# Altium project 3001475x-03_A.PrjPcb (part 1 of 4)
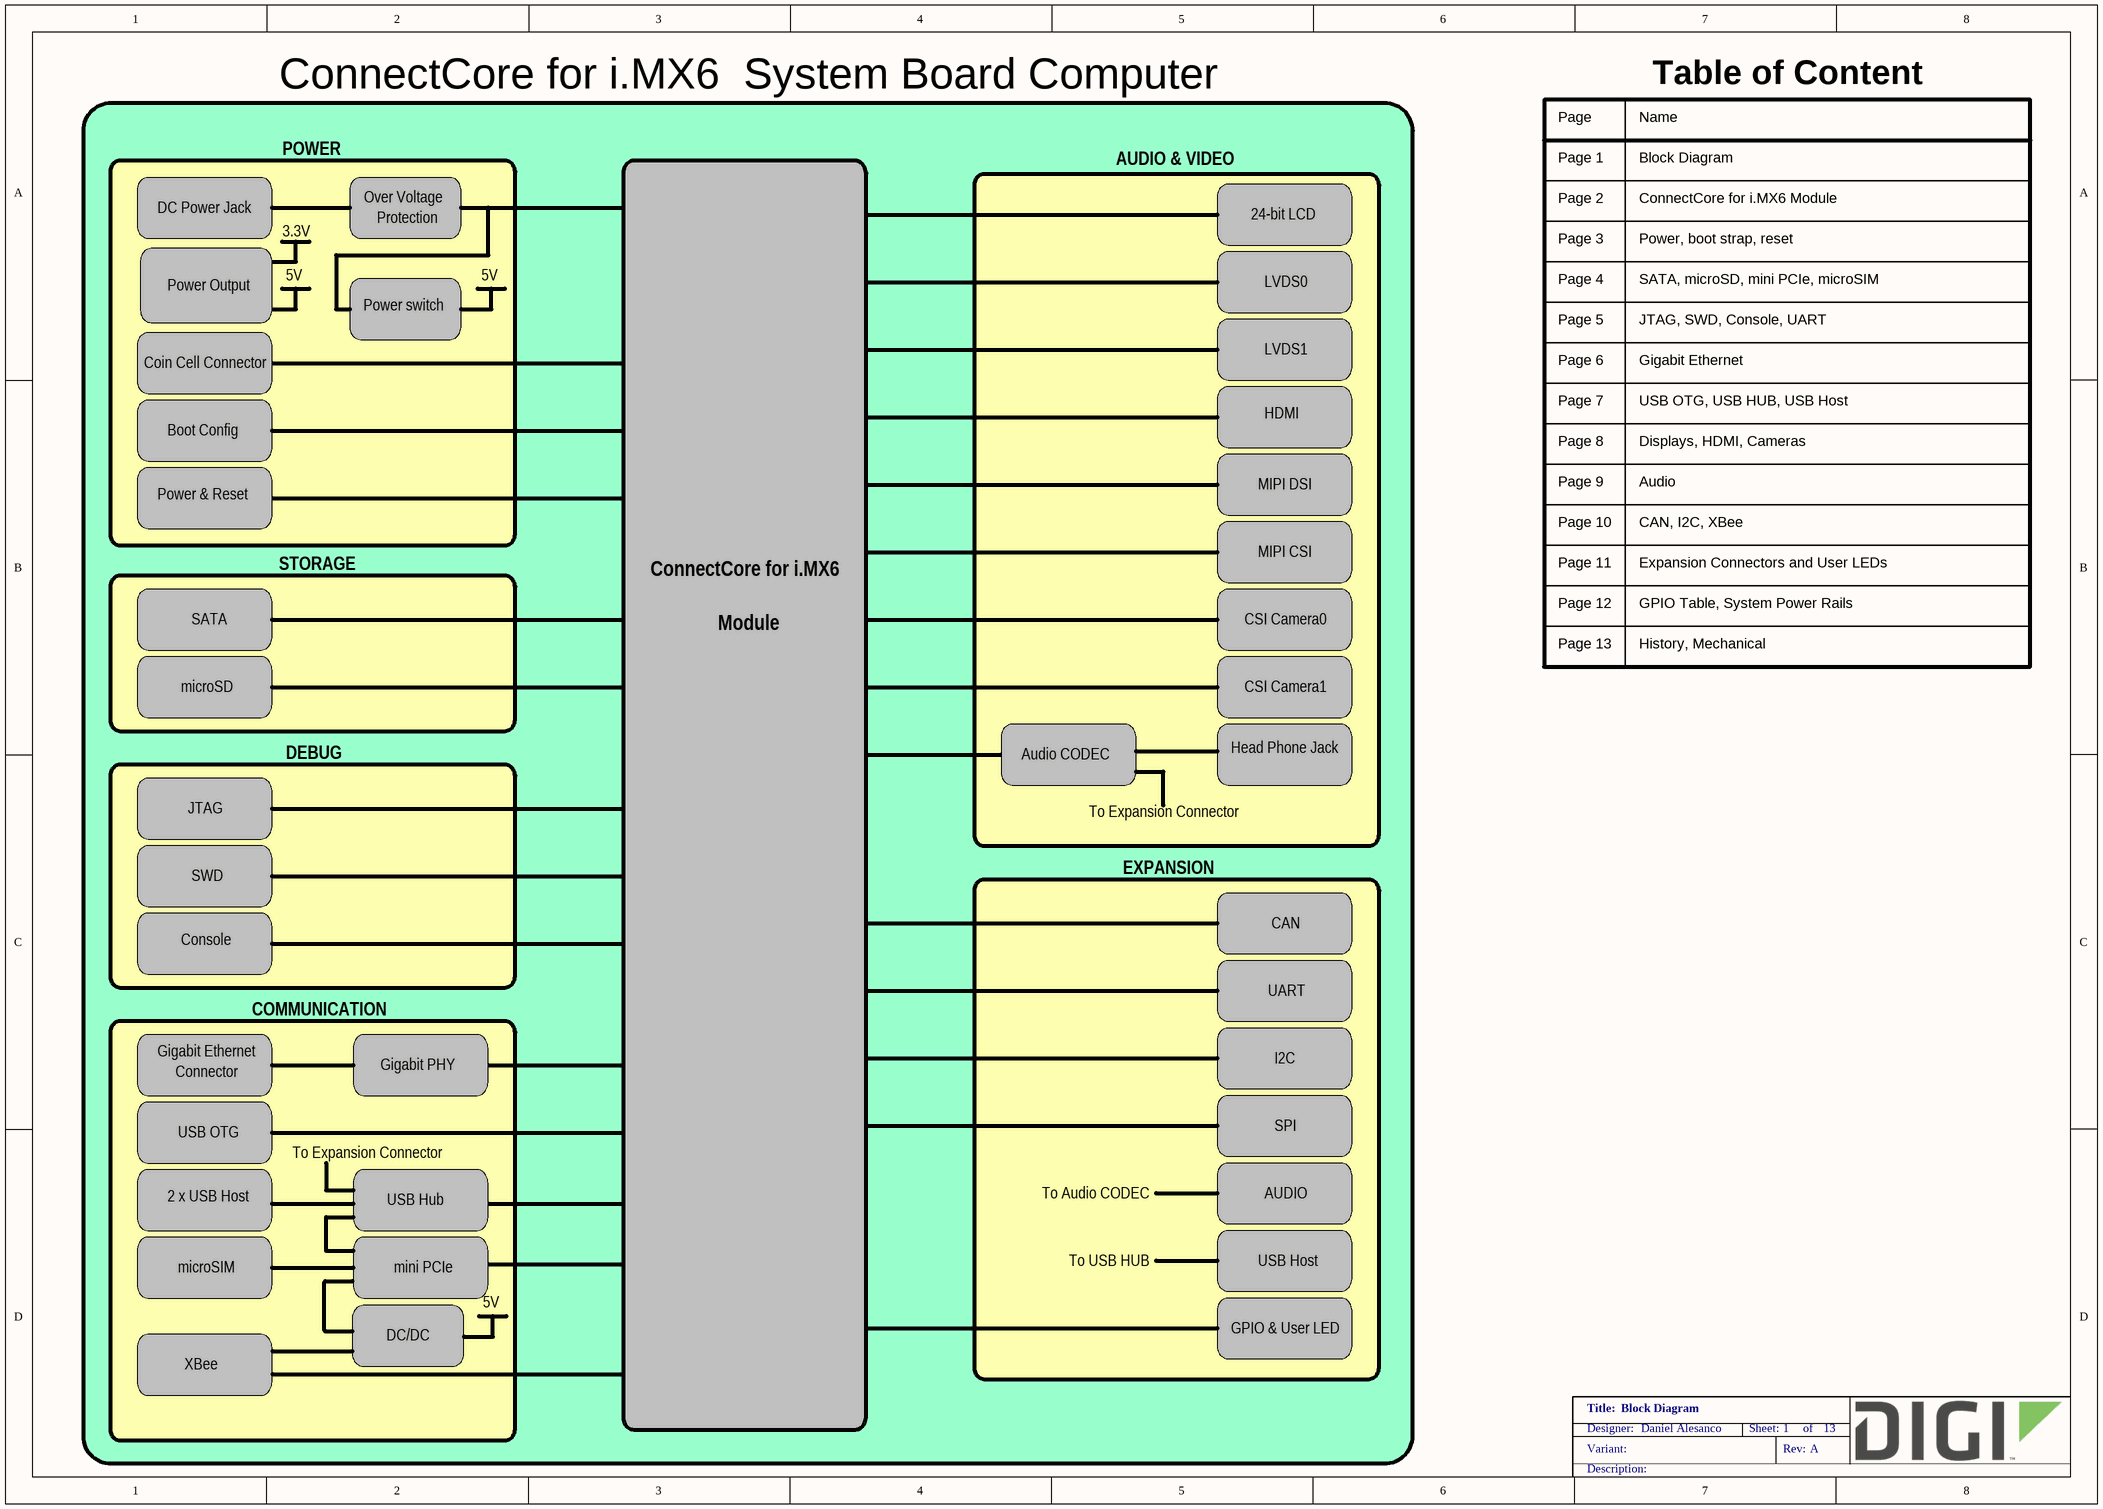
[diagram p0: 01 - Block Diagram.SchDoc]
VariantRevision: A
13 sheets, 433 parts. Net scope: flat (ports and power ports of the same name join across sheets).
Board file: 3001475x-03_A.PcbDoc
Sheets:
  01 - Block Diagram.SchDoc
  02 - CCIMX6 Module.SchDoc
  03 - Power, boot strap, reset.SchDoc
  04 - SATA, microSD, Mini PCIe, microSIM.SchDoc
  05 - JTAG, SWD, Console, UART.SchDoc
  06 - Gigabit Ethernet.SchDoc
  07 - USB OTG, USB HUB, USB Host.SchDoc
  08 - Displays, HDMI, Cameras.SchDoc
  09 - Audio.SchDoc
  10 - CAN, I2C, XBee.SchDoc
  11 - Expansion Connectors, User LEDs.SchDoc
  12 - GPIO Table, System Power rails.SchDoc
  13 - History, Mechanicals.SchDoc

## Sheet 01 - Block Diagram.SchDoc: Block Diagram
size A3; PageSetup: Record=PageOptions¦CenterHorizontal=True¦CenterVertical=True¦PrintScale=0.70¦XCorrection=1.00¦YCorrection=1.00¦PrintKind=0¦BorderSize=5000000¦LeftOffset=0¦BottomOffset=0¦Orientation=2¦PaperLength=4200¦PaperWidth=2970¦Scale=100¦PaperSource=7¦PrintQuality=600¦MediaType=1¦DitherType=10¦PaperKind=A4¦PrintScaleMode=1; Author: Daniel Alesanco; SheetNumber: 1; SheetTotal: 13

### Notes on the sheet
- ConnectCore for i.MX6  System Board Computer
- Table of Content
- POWER
- AUDIO & VIDEO
- Page 1
- Page
- Block Diagram
- Name
- DC Power Jack
- 3.3V
- Protection
- Over Voltage
- 24-bit LCD
- Page 2
- Page 3
- ConnectCore for i.MX6 Module
- Power, boot strap, reset
- Power Output
- 5V
- Power switch
- LVDS0
- Page 4
- SATA, microSD, mini PCIe, microSIM
- Coin Cell Connector
- LVDS1
- Page 5
- Page 6
- Gigabit Ethernet
- JTAG, SWD, Console, UART
- Boot Config
- HDMI
- Page 7
- Page 8
- Displays, HDMI, Cameras
- USB OTG, USB HUB, USB Host
- Power & Reset
- MIPI DSI
- Page 9
- Audio
- STORAGE
- ConnectCore for i.MX6
- MIPI CSI
- Page 10
- Page 11
- CAN, I2C, XBee
- Expansion Connectors and User LEDs
- SATA
- Module
- CSI Camera0
- Page 12
- Page 13
- GPIO Table, System Power Rails
- History, Mechanical
- microSD
- CSI Camera1
- DEBUG
- Audio CODEC
- Head Phone Jack
- JTAG
- To Expansion Connector
- SWD
- EXPANSION
- Console
- CAN
- COMMUNICATION
- UART
- Connector
- Gigabit PHY
- I2C
- USB OTG
- SPI
- 2 x USB Host
- USB Hub
- To Audio CODEC
- AUDIO
- microSIM
- mini PCIe
- To USB HUB
- USB Host
- XBee
- DC/DC
- GPIO & User LED

## Sheet 02 - CCIMX6 Module.SchDoc: ConnectCore for i.MX6 module
size A2; PageSetup: Record=PageOptions¦CenterHorizontal=True¦CenterVertical=True¦PrintScale=0.71¦XCorrection=1.00¦YCorrection=1.00¦PrintKind=0¦BorderSize=5000000¦LeftOffset=0¦BottomOffset=0¦Orientation=2¦PaperLength=4200¦PaperWidth=2970¦Scale=100¦PaperSource=7¦PrintQuality=600¦MediaType=1¦DitherType=10¦PaperKind=A3¦PrintScaleMode=1; Author: Daniel Alesanco; Organization: Altium Limited; Address1: L3, 12a Rodborough Rd; Address2: Frenchs Forest; Address3: NSW; Address4: Australia 2086; SheetNumber: 2; SheetTotal: 13
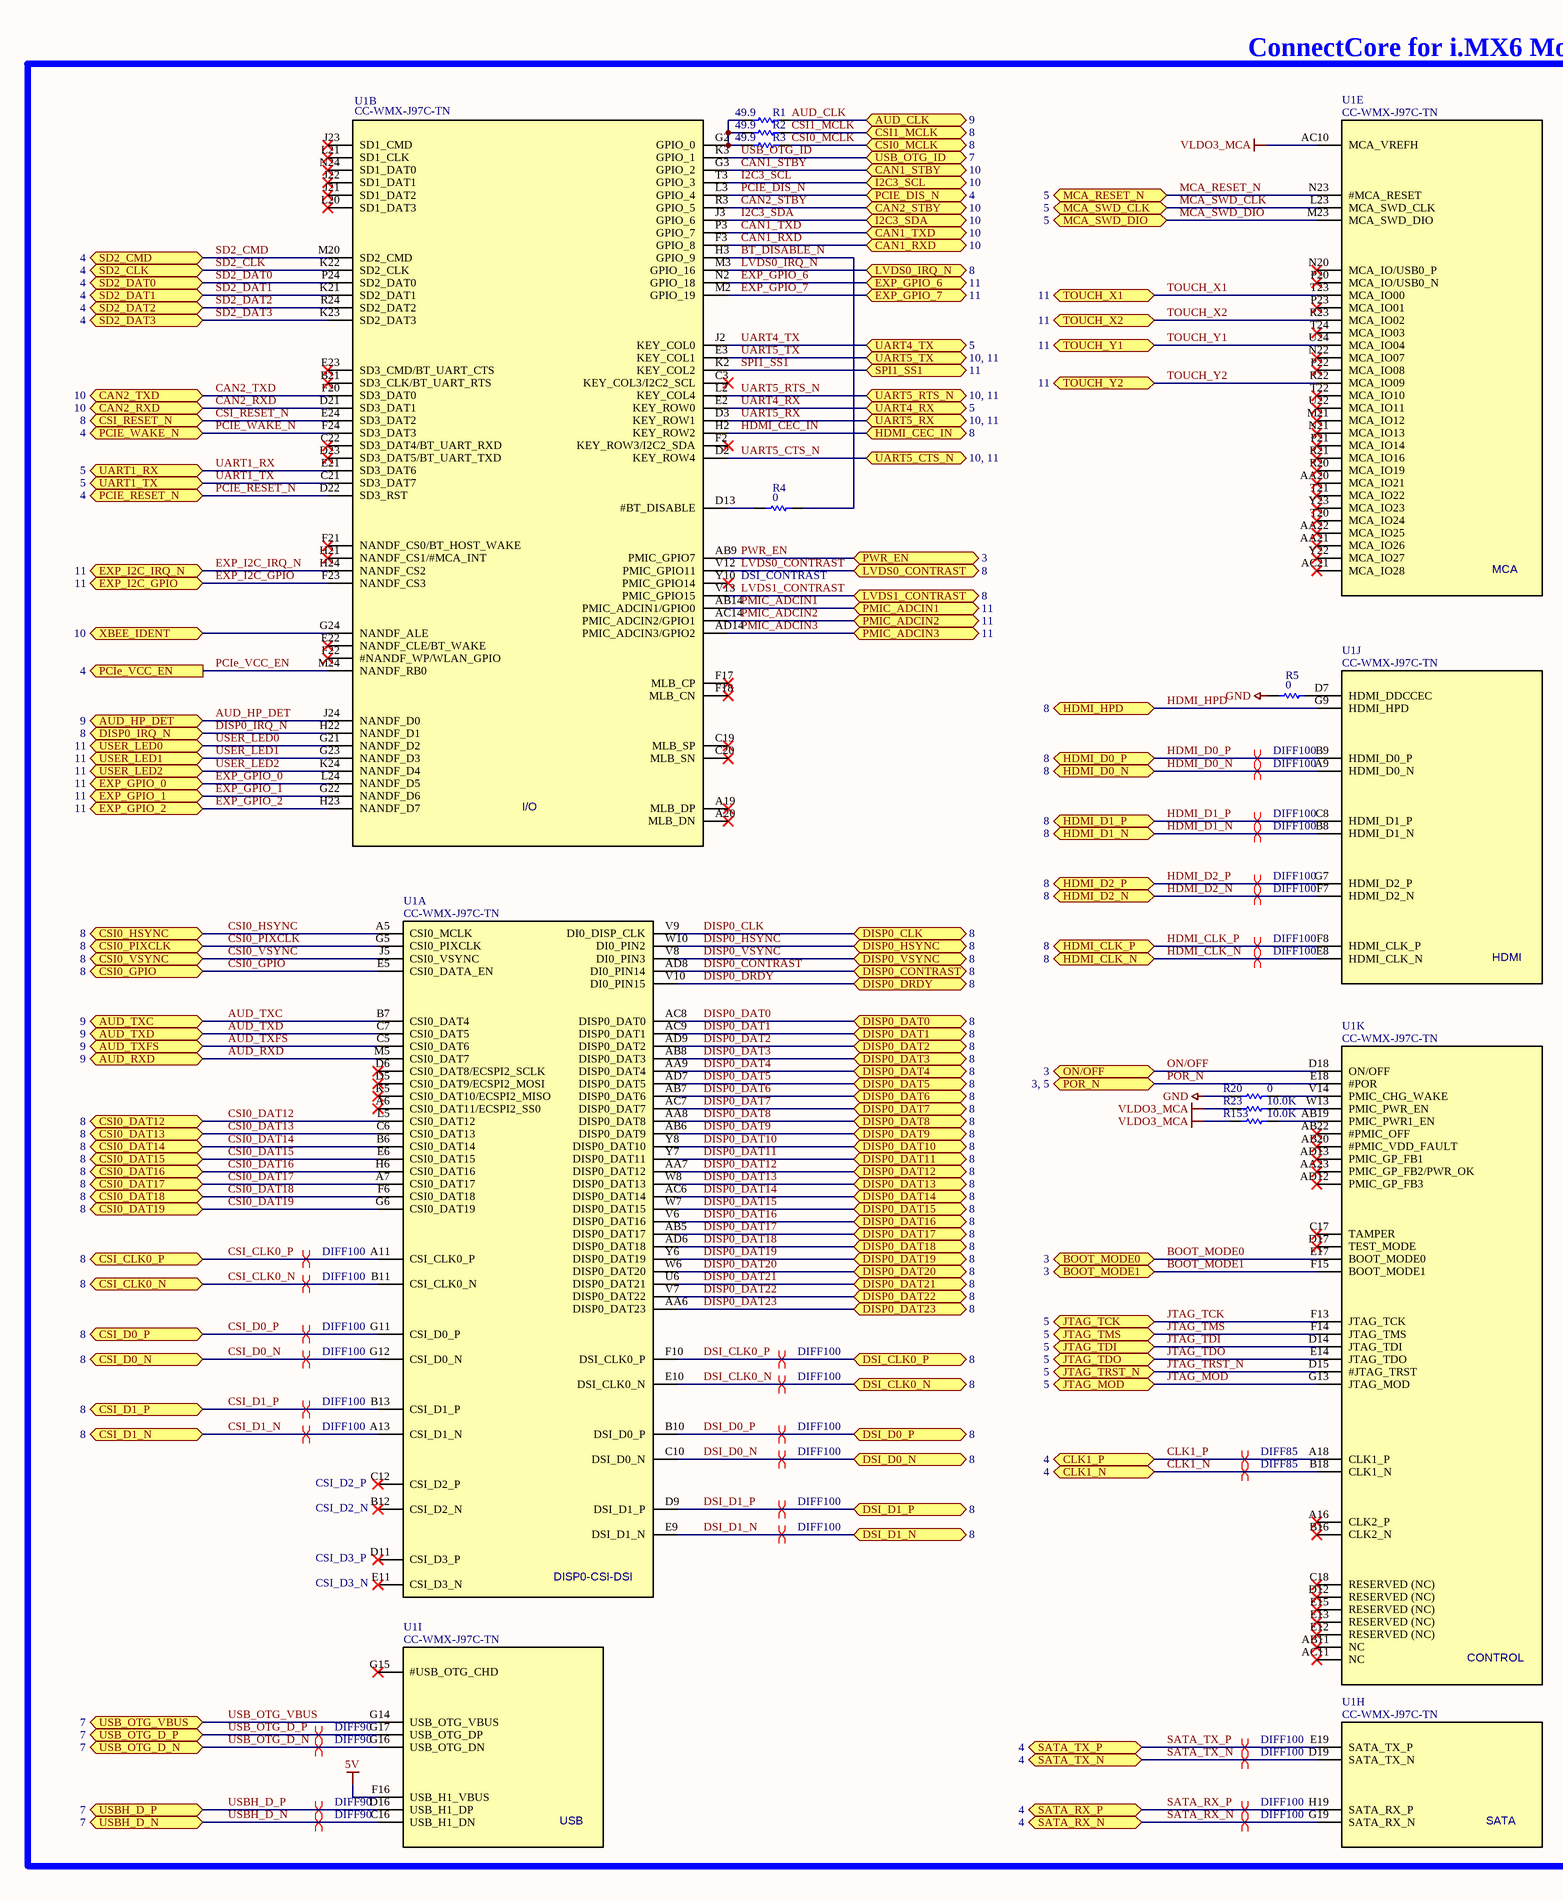
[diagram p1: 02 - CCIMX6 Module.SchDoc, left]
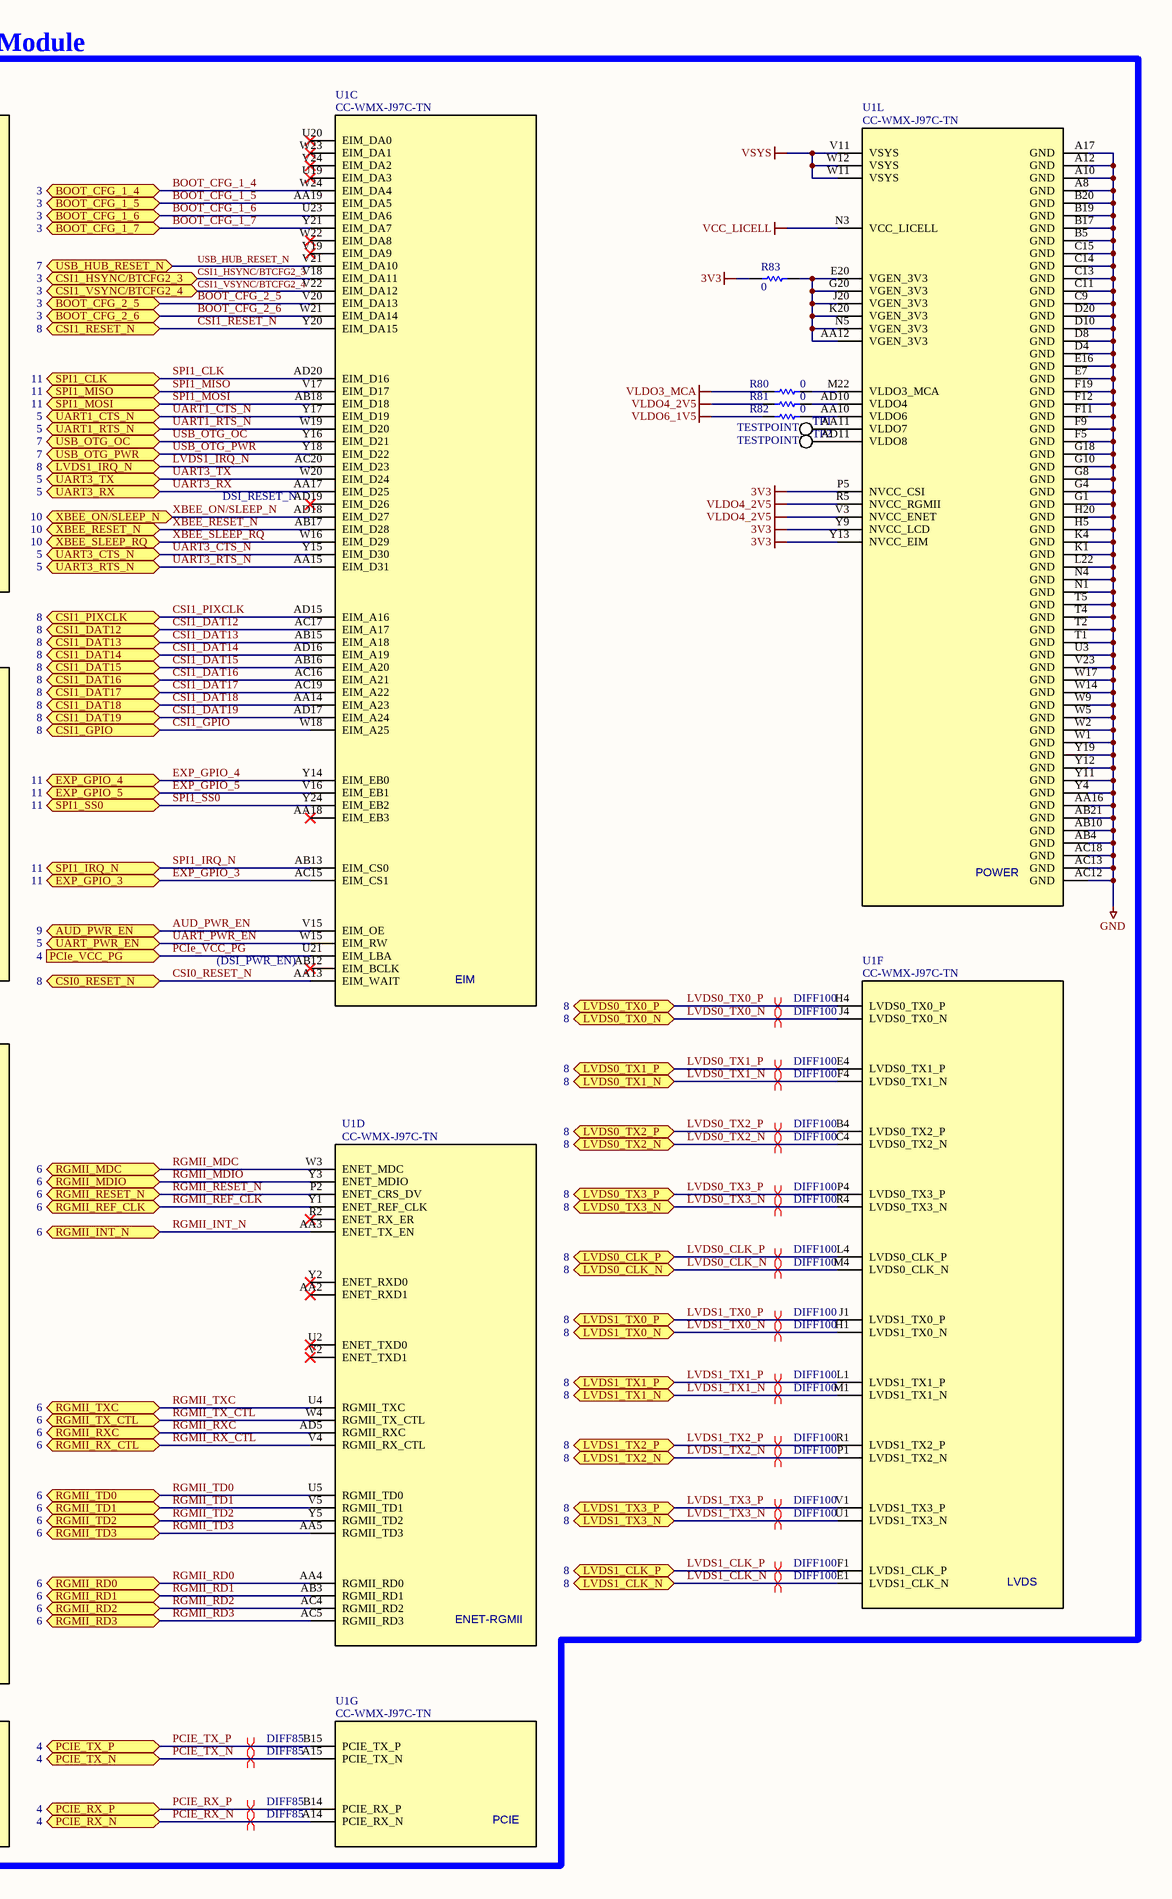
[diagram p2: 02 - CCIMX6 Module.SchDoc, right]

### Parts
R1  49.9  [RESC1005X40N]
R2  49.9  [RESC1005X40N]
R3  49.9  [RESC1005X40N]
R4  0  [RESC1005X40N]
R5  0  [RESC1005X40N]
R20  0  [RESC1005X40N]
R23  10.0K  [RESC1005X40N]
R80  0  [RESC1005X40N]
R81  0  [RESC1005X40N]
R82  0  [RESC1005X40N]
R83  0  [RESC1609X55N]
R153  10.0K  [RESC1005X40N]
TP1  TESTPOINT  [TP0762]  (no BOM)
TP2  TESTPOINT  [TP0762]  (no BOM)
U1  CC-WMX-J97C-TN  [MODULE_CCWMX6]  (parts A,B,C,D,E,F,G,H,I,J,K,L of 12)

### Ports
AUD_CLK (bidir, see 9), AUD_HP_DET (bidir, see 9), AUD_PWR_EN (bidir, see 9), AUD_RXD (bidir, see 9), AUD_TXC (bidir, see 9), AUD_TXD (bidir, see 9), AUD_TXFS (bidir, see 9), BOOT_CFG_1_4 (bidir, see 3), BOOT_CFG_1_5 (bidir, see 3), BOOT_CFG_1_6 (bidir, see 3), BOOT_CFG_1_7 (bidir, see 3), BOOT_CFG_2_5 (bidir, see 3), BOOT_CFG_2_6 (bidir, see 3), BOOT_MODE0 (bidir, see 3), BOOT_MODE1 (bidir, see 3), CAN1_RXD (bidir, see 10), CAN1_STBY (bidir, see 10), CAN1_TXD (bidir, see 10), CAN2_RXD (bidir, see 10), CAN2_STBY (bidir, see 10), CAN2_TXD (bidir, see 10), CLK1_N (bidir, see 4), CLK1_P (bidir, see 4), CSI0_DAT12 (bidir, see 8), CSI0_DAT13 (bidir, see 8), CSI0_DAT14 (bidir, see 8), CSI0_DAT15 (bidir, see 8), CSI0_DAT16 (bidir, see 8), CSI0_DAT17 (bidir, see 8), CSI0_DAT18 (bidir, see 8), CSI0_DAT19 (bidir, see 8), CSI0_GPIO (bidir, see 8), CSI0_HSYNC (bidir, see 8), CSI0_MCLK (bidir, see 8), CSI0_PIXCLK (bidir, see 8), CSI0_RESET_N (bidir, see 8), CSI0_VSYNC (bidir, see 8), CSI1_DAT12 (bidir, see 8), CSI1_DAT13 (bidir, see 8), CSI1_DAT14 (bidir, see 8), CSI1_DAT15 (bidir, see 8), CSI1_DAT16 (bidir, see 8), CSI1_DAT17 (bidir, see 8), CSI1_DAT18 (bidir, see 8), CSI1_DAT19 (bidir, see 8), CSI1_GPIO (bidir, see 8), CSI1_HSYNC/BTCFG2_3 (bidir, see 3), CSI1_MCLK (bidir, see 8), CSI1_PIXCLK (bidir, see 8), CSI1_RESET_N (bidir, see 8), CSI1_VSYNC/BTCFG2_4 (bidir, see 3), CSI_CLK0_N (bidir, see 8), CSI_CLK0_P (bidir, see 8), CSI_D0_N (bidir, see 8), CSI_D0_P (bidir, see 8), CSI_D1_N (bidir, see 8), CSI_D1_P (bidir, see 8), CSI_RESET_N (bidir, see 8), DISP0_CLK (bidir, see 8), DISP0_CONTRAST (bidir, see 8), DISP0_DAT0 (bidir, see 8), DISP0_DAT1 (bidir, see 8), DISP0_DAT2 (bidir, see 8), DISP0_DAT3 (bidir, see 8), DISP0_DAT4 (bidir, see 8), DISP0_DAT5 (bidir, see 8), DISP0_DAT6 (bidir, see 8), DISP0_DAT7 (bidir, see 8), DISP0_DAT8 (bidir, see 8), DISP0_DAT9 (bidir, see 8), DISP0_DAT10 (bidir, see 8), DISP0_DAT11 (bidir, see 8), DISP0_DAT12 (bidir, see 8), DISP0_DAT13 (bidir, see 8), DISP0_DAT14 (bidir, see 8), DISP0_DAT15 (bidir, see 8), DISP0_DAT16 (bidir, see 8), DISP0_DAT17 (bidir, see 8), DISP0_DAT18 (bidir, see 8), DISP0_DAT19 (bidir, see 8), DISP0_DAT20 (bidir, see 8), DISP0_DAT21 (bidir, see 8), DISP0_DAT22 (bidir, see 8), DISP0_DAT23 (bidir, see 8), DISP0_DRDY (bidir, see 8), DISP0_HSYNC (bidir, see 8), DISP0_IRQ_N (bidir, see 8), DISP0_VSYNC (bidir, see 8), DSI_CLK0_N (bidir, see 8), DSI_CLK0_P (bidir, see 8), DSI_D0_N (bidir, see 8), DSI_D0_P (bidir, see 8), DSI_D1_N (bidir, see 8), DSI_D1_P (bidir, see 8), EXP_GPIO_0 (bidir, see 11), EXP_GPIO_1 (bidir, see 11), EXP_GPIO_2 (bidir, see 11), EXP_GPIO_3 (bidir, see 11), EXP_GPIO_4 (bidir, see 11), EXP_GPIO_5 (bidir, see 11), EXP_GPIO_6 (bidir, see 11), EXP_GPIO_7 (bidir, see 11), EXP_I2C_GPIO (bidir, see 11), EXP_I2C_IRQ_N (bidir, see 11), HDMI_CEC_IN (bidir, see 8), HDMI_CLK_N (bidir, see 8), HDMI_CLK_P (bidir, see 8), HDMI_D0_N (bidir, see 8), HDMI_D0_P (bidir, see 8), HDMI_D1_N (bidir, see 8), HDMI_D1_P (bidir, see 8), HDMI_D2_N (bidir, see 8), HDMI_D2_P (bidir, see 8), HDMI_HPD (bidir, see 8), I2C3_SCL (bidir, see 10), I2C3_SDA (bidir, see 10), JTAG_MOD (bidir, see 5), JTAG_TCK (bidir, see 5), JTAG_TDI (bidir, see 5), JTAG_TDO (bidir, see 5), JTAG_TMS (bidir, see 5), JTAG_TRST_N (bidir, see 5), LVDS0_CLK_N (bidir, see 8), LVDS0_CLK_P (bidir, see 8), LVDS0_CONTRAST (bidir, see 8), LVDS0_IRQ_N (bidir, see 8), LVDS0_TX0_N (bidir, see 8), LVDS0_TX0_P (bidir, see 8), LVDS0_TX1_N (bidir, see 8), LVDS0_TX1_P (bidir, see 8), LVDS0_TX2_N (bidir, see 8), LVDS0_TX2_P (bidir, see 8), LVDS0_TX3_N (bidir, see 8), LVDS0_TX3_P (bidir, see 8), LVDS1_CLK_N (bidir, see 8), LVDS1_CLK_P (bidir, see 8), LVDS1_CONTRAST (bidir, see 8), LVDS1_IRQ_N (bidir, see 8), LVDS1_TX0_N (bidir, see 8), LVDS1_TX0_P (bidir, see 8), LVDS1_TX1_N (bidir, see 8), LVDS1_TX1_P (bidir, see 8), LVDS1_TX2_N (bidir, see 8), LVDS1_TX2_P (bidir, see 8), LVDS1_TX3_N (bidir, see 8), LVDS1_TX3_P (bidir, see 8), MCA_RESET_N (bidir, see 5), MCA_SWD_CLK (bidir, see 5), MCA_SWD_DIO (bidir, see 5), ON/OFF (bidir, see 3), PCIE_DIS_N (bidir, see 4), PCIE_RESET_N (bidir, see 4), PCIE_RX_N (bidir, see 4), PCIE_RX_P (bidir, see 4), PCIE_TX_N (bidir, see 4), PCIE_TX_P (bidir, see 4), PCIe_VCC_EN (out, see 4), PCIe_VCC_PG (in, see 4), PCIE_WAKE_N (bidir, see 4), PMIC_ADCIN1 (bidir, see 11), PMIC_ADCIN2 (bidir, see 11), PMIC_ADCIN3 (bidir, see 11), POR_N (bidir, see 3, 5), PWR_EN (bidir, see 3), RGMII_INT_N (bidir, see 6), RGMII_MDC (bidir, see 6), RGMII_MDIO (bidir, see 6), RGMII_RD0 (bidir, see 6), RGMII_RD1 (bidir, see 6), RGMII_RD2 (bidir, see 6), RGMII_RD3 (bidir, see 6), RGMII_REF_CLK (bidir, see 6), RGMII_RESET_N (bidir, see 6), RGMII_RX_CTL (bidir, see 6), RGMII_RXC (bidir, see 6), RGMII_TD0 (bidir, see 6), RGMII_TD1 (bidir, see 6), RGMII_TD2 (bidir, see 6), RGMII_TD3 (bidir, see 6), RGMII_TX_CTL (bidir, see 6), RGMII_TXC (bidir, see 6), SATA_RX_N (bidir, see 4), SATA_RX_P (bidir, see 4), SATA_TX_N (bidir, see 4), SATA_TX_P (bidir, see 4), SD2_CLK (bidir, see 4), SD2_CMD (bidir, see 4), SD2_DAT0 (bidir, see 4), SD2_DAT1 (bidir, see 4), SD2_DAT2 (bidir, see 4), SD2_DAT3 (bidir, see 4), SPI1_CLK (bidir, see 11), SPI1_IRQ_N (bidir, see 11), SPI1_MISO (bidir, see 11), SPI1_MOSI (bidir, see 11), SPI1_SS0 (bidir, see 11), SPI1_SS1 (bidir, see 11), TOUCH_X1 (bidir, see 11), TOUCH_X2 (bidir, see 11), TOUCH_Y1 (bidir, see 11), TOUCH_Y2 (bidir, see 11), UART1_CTS_N (bidir, see 5), UART1_RTS_N (bidir, see 5), UART1_RX (bidir, see 5), UART1_TX (bidir, see 5), UART3_CTS_N (bidir, see 5), UART3_RTS_N (bidir, see 5), UART3_RX (bidir, see 5), UART3_TX (bidir, see 5), UART4_RX (bidir, see 5), UART4_TX (bidir, see 5), UART5_CTS_N (bidir, see 10, 11), UART5_RTS_N (bidir, see 10, 11), UART5_RX (bidir, see 10, 11), UART5_TX (bidir, see 10, 11), UART_PWR_EN (bidir, see 5), USB_HUB_RESET_N (bidir, see 7), USB_OTG_D_N (bidir, see 7), USB_OTG_D_P (bidir, see 7), USB_OTG_ID (bidir, see 7), USB_OTG_OC (bidir, see 7), USB_OTG_PWR (bidir, see 7), USB_OTG_VBUS (bidir, see 7), USBH_D_N (bidir, see 7), USBH_D_P (bidir, see 7), USER_LED0 (bidir, see 11), USER_LED1 (bidir, see 11), USER_LED2 (bidir, see 11), XBEE_IDENT (bidir, see 10), XBEE_ON/SLEEP_N (bidir, see 10), XBEE_RESET_N (bidir, see 10), XBEE_SLEEP_RQ (bidir, see 10)

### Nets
3V3: R83.1 U1.P5(NVCC_CSI) U1.Y9(NVCC_LCD) U1.Y13(NVCC_EIM)
5V: U1.F16(USB_H1_VBUS)
GND: R5.1 R20.1 U1.A8(GND) U1.A10(GND) U1.A12(GND) U1.A17(GND) U1.AA16(GND) U1.AB4(GND) U1.AB10(GND) U1.AB21(GND) U1.AC12(GND) U1.AC13(GND) U1.AC18(GND) U1.B5(GND) U1.B17(GND) U1.B19(GND) U1.B20(GND) U1.C9(GND) U1.C11(GND) U1.C13(GND) U1.C14(GND) U1.C15(GND) U1.D4(GND) U1.D8(GND) U1.D10(GND) U1.D20(GND) U1.E7(GND) U1.E16(GND) U1.F5(GND) U1.F9(GND) U1.F11(GND) U1.F12(GND) U1.F19(GND) U1.G1(GND) U1.G4(GND) U1.G8(GND) U1.G10(GND) U1.G18(GND) U1.H5(GND) U1.H20(GND) U1.K1(GND) U1.K4(GND) U1.L22(GND) U1.N1(GND) U1.N4(GND) U1.T1(GND) U1.T2(GND) U1.T4(GND) U1.T5(GND) U1.U3(GND) U1.V23(GND) U1.W1(GND) U1.W2(GND) U1.W5(GND) U1.W9(GND) U1.W14(GND) U1.W17(GND) U1.Y4(GND) U1.Y11(GND) U1.Y12(GND) U1.Y19(GND)
VCC_LICELL: U1.N3(VCC_LICELL)
VLDO3_MCA: R23.2 R80.1 R153.2 U1.AC10(MCA_VREFH)
VLDO4_2V5: R81.1 U1.R5(NVCC_RGMII) U1.V3(NVCC_ENET)
VLDO6_1V5: R82.1
VSYS: U1.V11(VSYS) U1.W11(VSYS) U1.W12(VSYS)
AUD_CLK: R1.2 ; port AUD_CLK
AUD_HP_DET: U1.J24(NANDF_D0) ; port AUD_HP_DET
AUD_PWR_EN: U1.V15(EIM_OE) ; port AUD_PWR_EN
AUD_RXD: U1.M5(CSI0_DAT7) ; port AUD_RXD
AUD_TXC: U1.B7(CSI0_DAT4) ; port AUD_TXC
AUD_TXD: U1.C7(CSI0_DAT5) ; port AUD_TXD
AUD_TXFS: U1.C5(CSI0_DAT6) ; port AUD_TXFS
BOOT_CFG_1_4: U1.W24(EIM_DA4) ; port BOOT_CFG_1_4
BOOT_CFG_1_5: U1.AA19(EIM_DA5) ; port BOOT_CFG_1_5
BOOT_CFG_1_6: U1.U23(EIM_DA6) ; port BOOT_CFG_1_6
BOOT_CFG_1_7: U1.Y21(EIM_DA7) ; port BOOT_CFG_1_7
BOOT_CFG_2_5: U1.V20(EIM_DA13) ; port BOOT_CFG_2_5
BOOT_CFG_2_6: U1.W21(EIM_DA14) ; port BOOT_CFG_2_6
BOOT_MODE0: U1.E17(BOOT_MODE0) ; port BOOT_MODE0
BOOT_MODE1: U1.F15(BOOT_MODE1) ; port BOOT_MODE1
BT_DISABLE_N: R4.2 U1.H3(GPIO_9)
CAN1_RXD: U1.F3(GPIO_8) ; port CAN1_RXD
CAN1_STBY: U1.G3(GPIO_2) ; port CAN1_STBY
CAN1_TXD: U1.P3(GPIO_7) ; port CAN1_TXD
CAN2_RXD: U1.D21(SD3_DAT1) ; port CAN2_RXD
CAN2_STBY: U1.R3(GPIO_5) ; port CAN2_STBY
CAN2_TXD: U1.F20(SD3_DAT0) ; port CAN2_TXD
CLK1_N: U1.B18(CLK1_N) ; port CLK1_N
CLK1_P: U1.A18(CLK1_P) ; port CLK1_P
CSI0_DAT12: U1.L5(CSI0_DAT12) ; port CSI0_DAT12
CSI0_DAT13: U1.C6(CSI0_DAT13) ; port CSI0_DAT13
CSI0_DAT14: U1.B6(CSI0_DAT14) ; port CSI0_DAT14
CSI0_DAT15: U1.E6(CSI0_DAT15) ; port CSI0_DAT15
CSI0_DAT16: U1.H6(CSI0_DAT16) ; port CSI0_DAT16
CSI0_DAT17: U1.A7(CSI0_DAT17) ; port CSI0_DAT17
CSI0_DAT18: U1.F6(CSI0_DAT18) ; port CSI0_DAT18
CSI0_DAT19: U1.G6(CSI0_DAT19) ; port CSI0_DAT19
CSI0_GPIO: U1.E5(CSI0_DATA_EN) ; port CSI0_GPIO
CSI0_HSYNC: U1.A5(CSI0_MCLK) ; port CSI0_HSYNC
CSI0_MCLK: R3.2 ; port CSI0_MCLK
CSI0_PIXCLK: U1.G5(CSI0_PIXCLK) ; port CSI0_PIXCLK
CSI0_RESET_N: U1.AA13(EIM_WAIT) ; port CSI0_RESET_N
CSI0_VSYNC: U1.J5(CSI0_VSYNC) ; port CSI0_VSYNC
CSI1_DAT12: U1.AC17(EIM_A17) ; port CSI1_DAT12
CSI1_DAT13: U1.AB15(EIM_A18) ; port CSI1_DAT13
CSI1_DAT14: U1.AD16(EIM_A19) ; port CSI1_DAT14
CSI1_DAT15: U1.AB16(EIM_A20) ; port CSI1_DAT15
CSI1_DAT16: U1.AC16(EIM_A21) ; port CSI1_DAT16
CSI1_DAT17: U1.AC19(EIM_A22) ; port CSI1_DAT17
CSI1_DAT18: U1.AA14(EIM_A23) ; port CSI1_DAT18
CSI1_DAT19: U1.AD17(EIM_A24) ; port CSI1_DAT19
CSI1_GPIO: U1.W18(EIM_A25) ; port CSI1_GPIO
CSI1_HSYNC/BTCFG2_3: U1.V18(EIM_DA11) ; port CSI1_HSYNC/BTCFG2_3
CSI1_MCLK: R2.2 ; port CSI1_MCLK
CSI1_PIXCLK: U1.AD15(EIM_A16) ; port CSI1_PIXCLK
CSI1_RESET_N: U1.Y20(EIM_DA15) ; port CSI1_RESET_N
CSI1_VSYNC/BTCFG2_4: U1.V22(EIM_DA12) ; port CSI1_VSYNC/BTCFG2_4
CSI_CLK0_N: U1.B11(CSI_CLK0_N) ; port CSI_CLK0_N
CSI_CLK0_P: U1.A11(CSI_CLK0_P) ; port CSI_CLK0_P
CSI_D0_N: U1.G12(CSI_D0_N) ; port CSI_D0_N
CSI_D0_P: U1.G11(CSI_D0_P) ; port CSI_D0_P
CSI_D1_N: U1.A13(CSI_D1_N) ; port CSI_D1_N
CSI_D1_P: U1.B13(CSI_D1_P) ; port CSI_D1_P
CSI_RESET_N: U1.E24(SD3_DAT2) ; port CSI_RESET_N
DISP0_CLK: U1.V9(DI0_DISP_CLK) ; port DISP0_CLK
DISP0_CONTRAST: U1.AD8(DI0_PIN14) ; port DISP0_CONTRAST
DISP0_DAT0: U1.AC8(DISP0_DAT0) ; port DISP0_DAT0
DISP0_DAT1: U1.AC9(DISP0_DAT1) ; port DISP0_DAT1
DISP0_DAT2: U1.AD9(DISP0_DAT2) ; port DISP0_DAT2
DISP0_DAT3: U1.AB8(DISP0_DAT3) ; port DISP0_DAT3
DISP0_DAT4: U1.AA9(DISP0_DAT4) ; port DISP0_DAT4
DISP0_DAT5: U1.AD7(DISP0_DAT5) ; port DISP0_DAT5
DISP0_DAT6: U1.AB7(DISP0_DAT6) ; port DISP0_DAT6
DISP0_DAT7: U1.AC7(DISP0_DAT7) ; port DISP0_DAT7
DISP0_DAT8: U1.AA8(DISP0_DAT8) ; port DISP0_DAT8
DISP0_DAT9: U1.AB6(DISP0_DAT9) ; port DISP0_DAT9
DISP0_DAT10: U1.Y8(DISP0_DAT10) ; port DISP0_DAT10
DISP0_DAT11: U1.Y7(DISP0_DAT11) ; port DISP0_DAT11
DISP0_DAT12: U1.AA7(DISP0_DAT12) ; port DISP0_DAT12
DISP0_DAT13: U1.W8(DISP0_DAT13) ; port DISP0_DAT13
DISP0_DAT14: U1.AC6(DISP0_DAT14) ; port DISP0_DAT14
DISP0_DAT15: U1.W7(DISP0_DAT15) ; port DISP0_DAT15
DISP0_DAT16: U1.V6(DISP0_DAT16) ; port DISP0_DAT16
DISP0_DAT17: U1.AB5(DISP0_DAT17) ; port DISP0_DAT17
DISP0_DAT18: U1.AD6(DISP0_DAT18) ; port DISP0_DAT18
DISP0_DAT19: U1.Y6(DISP0_DAT19) ; port DISP0_DAT19
DISP0_DAT20: U1.W6(DISP0_DAT20) ; port DISP0_DAT20
DISP0_DAT21: U1.U6(DISP0_DAT21) ; port DISP0_DAT21
DISP0_DAT22: U1.V7(DISP0_DAT22) ; port DISP0_DAT22
DISP0_DAT23: U1.AA6(DISP0_DAT23) ; port DISP0_DAT23
DISP0_DRDY: U1.V10(DI0_PIN15) ; port DISP0_DRDY
DISP0_HSYNC: U1.W10(DI0_PIN2) ; port DISP0_HSYNC
DISP0_IRQ_N: U1.H22(NANDF_D1) ; port DISP0_IRQ_N
DISP0_VSYNC: U1.V8(DI0_PIN3) ; port DISP0_VSYNC
DSI_CLK0_N: U1.E10(DSI_CLK0_N) ; port DSI_CLK0_N
DSI_CLK0_P: U1.F10(DSI_CLK0_P) ; port DSI_CLK0_P
DSI_D0_N: U1.C10(DSI_D0_N) ; port DSI_D0_N
DSI_D0_P: U1.B10(DSI_D0_P) ; port DSI_D0_P
DSI_D1_N: U1.E9(DSI_D1_N) ; port DSI_D1_N
DSI_D1_P: U1.D9(DSI_D1_P) ; port DSI_D1_P
EXP_GPIO_0: U1.L24(NANDF_D5) ; port EXP_GPIO_0
EXP_GPIO_1: U1.G22(NANDF_D6) ; port EXP_GPIO_1
EXP_GPIO_2: U1.H23(NANDF_D7) ; port EXP_GPIO_2
EXP_GPIO_3: U1.AC15(EIM_CS1) ; port EXP_GPIO_3
EXP_GPIO_4: U1.Y14(EIM_EB0) ; port EXP_GPIO_4
EXP_GPIO_5: U1.V16(EIM_EB1) ; port EXP_GPIO_5
EXP_GPIO_6: U1.N2(GPIO_18) ; port EXP_GPIO_6
EXP_GPIO_7: U1.M2(GPIO_19) ; port EXP_GPIO_7
EXP_I2C_GPIO: U1.F23(NANDF_CS3) ; port EXP_I2C_GPIO
EXP_I2C_IRQ_N: U1.H24(NANDF_CS2) ; port EXP_I2C_IRQ_N
HDMI_CEC_IN: U1.H2(KEY_ROW2) ; port HDMI_CEC_IN
HDMI_CLK_N: U1.E8(HDMI_CLK_N) ; port HDMI_CLK_N
HDMI_CLK_P: U1.F8(HDMI_CLK_P) ; port HDMI_CLK_P
HDMI_D0_N: U1.A9(HDMI_D0_N) ; port HDMI_D0_N
HDMI_D0_P: U1.B9(HDMI_D0_P) ; port HDMI_D0_P
HDMI_D1_N: U1.B8(HDMI_D1_N) ; port HDMI_D1_N
HDMI_D1_P: U1.C8(HDMI_D1_P) ; port HDMI_D1_P
HDMI_D2_N: U1.F7(HDMI_D2_N) ; port HDMI_D2_N
HDMI_D2_P: U1.G7(HDMI_D2_P) ; port HDMI_D2_P
HDMI_HPD: U1.G9(HDMI_HPD) ; port HDMI_HPD
I2C3_SCL: U1.T3(GPIO_3) ; port I2C3_SCL
I2C3_SDA: U1.J3(GPIO_6) ; port I2C3_SDA
JTAG_MOD: U1.G13(JTAG_MOD) ; port JTAG_MOD
JTAG_TCK: U1.F13(JTAG_TCK) ; port JTAG_TCK
JTAG_TDI: U1.D14(JTAG_TDI) ; port JTAG_TDI
JTAG_TDO: U1.E14(JTAG_TDO) ; port JTAG_TDO
JTAG_TMS: U1.F14(JTAG_TMS) ; port JTAG_TMS
JTAG_TRST_N: U1.D15(#JTAG_TRST) ; port JTAG_TRST_N
LVDS0_CLK_N: U1.M4(LVDS0_CLK_N) ; port LVDS0_CLK_N
LVDS0_CLK_P: U1.L4(LVDS0_CLK_P) ; port LVDS0_CLK_P
LVDS0_CONTRAST: U1.V12(PMIC_GPIO11) ; port LVDS0_CONTRAST
LVDS0_IRQ_N: U1.M3(GPIO_16) ; port LVDS0_IRQ_N
LVDS0_TX0_N: U1.J4(LVDS0_TX0_N) ; port LVDS0_TX0_N
LVDS0_TX0_P: U1.H4(LVDS0_TX0_P) ; port LVDS0_TX0_P
LVDS0_TX1_N: U1.F4(LVDS0_TX1_N) ; port LVDS0_TX1_N
LVDS0_TX1_P: U1.E4(LVDS0_TX1_P) ; port LVDS0_TX1_P
LVDS0_TX2_N: U1.C4(LVDS0_TX2_N) ; port LVDS0_TX2_N
LVDS0_TX2_P: U1.B4(LVDS0_TX2_P) ; port LVDS0_TX2_P
LVDS0_TX3_N: U1.R4(LVDS0_TX3_N) ; port LVDS0_TX3_N
LVDS0_TX3_P: U1.P4(LVDS0_TX3_P) ; port LVDS0_TX3_P
LVDS1_CLK_N: U1.E1(LVDS1_CLK_N) ; port LVDS1_CLK_N
LVDS1_CLK_P: U1.F1(LVDS1_CLK_P) ; port LVDS1_CLK_P
LVDS1_CONTRAST: U1.V13(PMIC_GPIO15) ; port LVDS1_CONTRAST
LVDS1_IRQ_N: U1.AC20(EIM_D23) ; port LVDS1_IRQ_N
LVDS1_TX0_N: U1.H1(LVDS1_TX0_N) ; port LVDS1_TX0_N
LVDS1_TX0_P: U1.J1(LVDS1_TX0_P) ; port LVDS1_TX0_P
LVDS1_TX1_N: U1.M1(LVDS1_TX1_N) ; port LVDS1_TX1_N
LVDS1_TX1_P: U1.L1(LVDS1_TX1_P) ; port LVDS1_TX1_P
LVDS1_TX2_N: U1.P1(LVDS1_TX2_N) ; port LVDS1_TX2_N
LVDS1_TX2_P: U1.R1(LVDS1_TX2_P) ; port LVDS1_TX2_P
LVDS1_TX3_N: U1.U1(LVDS1_TX3_N) ; port LVDS1_TX3_N
LVDS1_TX3_P: U1.V1(LVDS1_TX3_P) ; port LVDS1_TX3_P
MCA_RESET_N: U1.N23(#MCA_RESET) ; port MCA_RESET_N
MCA_SWD_CLK: U1.L23(MCA_SWD_CLK) ; port MCA_SWD_CLK
MCA_SWD_DIO: U1.M23(MCA_SWD_DIO) ; port MCA_SWD_DIO
ON/OFF: U1.D18(ON/OFF) ; port ON/OFF
PCIE_DIS_N: U1.L3(GPIO_4) ; port PCIE_DIS_N
PCIE_RESET_N: U1.D22(SD3_RST) ; port PCIE_RESET_N
PCIE_RX_N: U1.A14(PCIE_RX_N) ; port PCIE_RX_N
PCIE_RX_P: U1.B14(PCIE_RX_P) ; port PCIE_RX_P
PCIE_TX_N: U1.A15(PCIE_TX_N) ; port PCIE_TX_N
PCIE_TX_P: U1.B15(PCIE_TX_P) ; port PCIE_TX_P
PCIe_VCC_EN: U1.M24(NANDF_RB0) ; port PCIe_VCC_EN
PCIe_VCC_PG: U1.U21(EIM_LBA) ; port PCIe_VCC_PG
PCIE_WAKE_N: U1.F24(SD3_DAT3) ; port PCIE_WAKE_N
PMIC_ADCIN1: U1.AB14(PMIC_ADCIN1/GPIO0) ; port PMIC_ADCIN1
PMIC_ADCIN2: U1.AC14(PMIC_ADCIN2/GPIO1) ; port PMIC_ADCIN2
PMIC_ADCIN3: U1.AD14(PMIC_ADCIN3/GPIO2) ; port PMIC_ADCIN3
POR_N: U1.E18(#POR) ; port POR_N
PWR_EN: U1.AB9(PMIC_GPIO7) ; port PWR_EN
RGMII_INT_N: U1.AA3(ENET_TX_EN) ; port RGMII_INT_N
RGMII_MDC: U1.W3(ENET_MDC) ; port RGMII_MDC
RGMII_MDIO: U1.Y3(ENET_MDIO) ; port RGMII_MDIO
RGMII_RD0: U1.AA4(RGMII_RD0) ; port RGMII_RD0
RGMII_RD1: U1.AB3(RGMII_RD1) ; port RGMII_RD1
RGMII_RD2: U1.AC4(RGMII_RD2) ; port RGMII_RD2
RGMII_RD3: U1.AC5(RGMII_RD3) ; port RGMII_RD3
RGMII_REF_CLK: U1.Y1(ENET_REF_CLK) ; port RGMII_REF_CLK
RGMII_RESET_N: U1.P2(ENET_CRS_DV) ; port RGMII_RESET_N
RGMII_RX_CTL: U1.V4(RGMII_RX_CTL) ; port RGMII_RX_CTL
RGMII_RXC: U1.AD5(RGMII_RXC) ; port RGMII_RXC
RGMII_TD0: U1.U5(RGMII_TD0) ; port RGMII_TD0
RGMII_TD1: U1.V5(RGMII_TD1) ; port RGMII_TD1
RGMII_TD2: U1.Y5(RGMII_TD2) ; port RGMII_TD2
RGMII_TD3: U1.AA5(RGMII_TD3) ; port RGMII_TD3
RGMII_TX_CTL: U1.W4(RGMII_TX_CTL) ; port RGMII_TX_CTL
RGMII_TXC: U1.U4(RGMII_TXC) ; port RGMII_TXC
SATA_RX_N: U1.G19(SATA_RX_N) ; port SATA_RX_N
SATA_RX_P: U1.H19(SATA_RX_P) ; port SATA_RX_P
SATA_TX_N: U1.D19(SATA_TX_N) ; port SATA_TX_N
SATA_TX_P: U1.E19(SATA_TX_P) ; port SATA_TX_P
SD2_CLK: U1.K22(SD2_CLK) ; port SD2_CLK
SD2_CMD: U1.M20(SD2_CMD) ; port SD2_CMD
SD2_DAT0: U1.P24(SD2_DAT0) ; port SD2_DAT0
SD2_DAT1: U1.K21(SD2_DAT1) ; port SD2_DAT1
SD2_DAT2: U1.R24(SD2_DAT2) ; port SD2_DAT2
SD2_DAT3: U1.K23(SD2_DAT3) ; port SD2_DAT3
SPI1_CLK: U1.AD20(EIM_D16) ; port SPI1_CLK
SPI1_IRQ_N: U1.AB13(EIM_CS0) ; port SPI1_IRQ_N
SPI1_MISO: U1.V17(EIM_D17) ; port SPI1_MISO
SPI1_MOSI: U1.AB18(EIM_D18) ; port SPI1_MOSI
SPI1_SS0: U1.Y24(EIM_EB2) ; port SPI1_SS0
SPI1_SS1: U1.K2(KEY_COL2) ; port SPI1_SS1
TOUCH_X1: U1.T23(MCA_IO00) ; port TOUCH_X1
TOUCH_X2: U1.R23(MCA_IO02) ; port TOUCH_X2
TOUCH_Y1: U1.U24(MCA_IO04) ; port TOUCH_Y1
TOUCH_Y2: U1.R22(MCA_IO09) ; port TOUCH_Y2
UART1_CTS_N: U1.Y17(EIM_D19) ; port UART1_CTS_N
UART1_RTS_N: U1.W19(EIM_D20) ; port UART1_RTS_N
UART1_RX: U1.E21(SD3_DAT6) ; port UART1_RX
UART1_TX: U1.C21(SD3_DAT7) ; port UART1_TX
UART3_CTS_N: U1.Y15(EIM_D30) ; port UART3_CTS_N
UART3_RTS_N: U1.AA15(EIM_D31) ; port UART3_RTS_N
UART3_RX: U1.AA17(EIM_D25) ; port UART3_RX
UART3_TX: U1.W20(EIM_D24) ; port UART3_TX
UART4_RX: U1.E2(KEY_ROW0) ; port UART4_RX
UART4_TX: U1.J2(KEY_COL0) ; port UART4_TX
UART5_CTS_N: U1.D2(KEY_ROW4) ; port UART5_CTS_N
UART5_RTS_N: U1.L2(KEY_COL4) ; port UART5_RTS_N
UART5_RX: U1.D3(KEY_ROW1) ; port UART5_RX
UART5_TX: U1.E3(KEY_COL1) ; port UART5_TX
UART_PWR_EN: U1.W15(EIM_RW) ; port UART_PWR_EN
USB_HUB_RESET_N: U1.V21(EIM_DA10) ; port USB_HUB_RESET_N
USB_OTG_D_N: U1.G16(USB_OTG_DN) ; port USB_OTG_D_N
USB_OTG_D_P: U1.G17(USB_OTG_DP) ; port USB_OTG_D_P
USB_OTG_ID: U1.K3(GPIO_1) ; port USB_OTG_ID
USB_OTG_OC: U1.Y16(EIM_D21) ; port USB_OTG_OC
USB_OTG_PWR: U1.Y18(EIM_D22) ; port USB_OTG_PWR
USB_OTG_VBUS: U1.G14(USB_OTG_VBUS) ; port USB_OTG_VBUS
USBH_D_N: U1.C16(USB_H1_DN) ; port USBH_D_N
USBH_D_P: U1.D16(USB_H1_DP) ; port USBH_D_P
USER_LED0: U1.G21(NANDF_D2) ; port USER_LED0
USER_LED1: U1.G23(NANDF_D3) ; port USER_LED1
USER_LED2: U1.K24(NANDF_D4) ; port USER_LED2
XBEE_IDENT: U1.G24(NANDF_ALE) ; port XBEE_IDENT
XBEE_ON/SLEEP_N: U1.AD18(EIM_D27) ; port XBEE_ON/SLEEP_N
XBEE_RESET_N: U1.AB17(EIM_D28) ; port XBEE_RESET_N
XBEE_SLEEP_RQ: U1.W16(EIM_D29) ; port XBEE_SLEEP_RQ
NetR1_1: R1.1 R2.1 R3.1 U1.G2(GPIO_0)
NetR4_1: R4.1 U1.D13(#BT_DISABLE)
NetR5_2: R5.2 U1.D7(HDMI_DDCCEC)
NetR20_2: R20.2 U1.V14(PMIC_CHG_WAKE)
NetR23_1: R23.1 U1.W13(PMIC_PWR_EN)
NetR80_2: R80.2 U1.M22(VLDO3_MCA)
NetR81_2: R81.2 U1.AD10(VLDO4)
NetR82_2: R82.2 U1.AA10(VLDO6)
NetR83_2: R83.2 U1.AA12(VGEN_3V3) U1.E20(VGEN_3V3) U1.G20(VGEN_3V3) U1.J20(VGEN_3V3) U1.K20(VGEN_3V3) U1.N5(VGEN_3V3)
NetR153_1: R153.1 U1.AB19(PMIC_PWR1_EN)
NetTP1_1: TP1.1 U1.AA11(VLDO7)
NetTP2_1: TP2.1 U1.AD11(VLDO8)

Not connected (* = marked no-connect by the designer): U1 A6(CSI0_DAT11/ECSPI2_SS0)* A16(CLK2_P)* A19(MLB_DP)* A20(MLB_DN)* AA2(ENET_RXD1)* AA18(EIM_EB3)* AA20(MCA_IO21)* AA21(MCA_IO26)* AA22(MCA_IO25)* AA23(PMIC_GP_FB2/PWR_OK)* AB11(NC)* AB12(EIM_BCLK)* AB20(#PMIC_VDD_FAULT)* AB22(#PMIC_OFF)* AC11(NC)* AC21(MCA_IO28)* AD12(PMIC_GP_FB3)* AD13(PMIC_GP_FB1)* AD19(EIM_D26)* B12(CSI_D2_N)* B16(CLK2_N)* B21(SD3_CLK/BT_UART_RTS)* C3(KEY_COL3/I2C2_SCL)* C12(CSI_D2_P)* C17(TAMPER)* C18(RESERVED_(NC))* C19(MLB_SP)* C20(MLB_SN)* C22(SD3_DAT4/BT_UART_RXD)* D5(CSI0_DAT9/ECSPI2_MOSI)* D6(CSI0_DAT8/ECSPI2_SCLK)* D11(CSI_D3_P)* D12(RESERVED_(NC))* D17(TEST_MODE)* D23(SD3_DAT5/BT_UART_TXD)* E11(CSI_D3_N)* E12(RESERVED_(NC))* E13(RESERVED_(NC))* E15(RESERVED_(NC))* E22(NANDF_CLE/BT_WAKE)* E23(SD3_CMD/BT_UART_CTS)* F2(KEY_ROW3/I2C2_SDA)* F17(MLB_CP)* F18(MLB_CN)* F21(NANDF_CS0/BT_HOST_WAKE)* F22(#NANDF_WP/WLAN_GPIO)* G15(#USB_OTG_CHD)* H21(NANDF_CS1/#MCA_INT)* J21(SD1_DAT2)* J22(SD1_DAT1)* J23(SD1_CMD)* K5(CSI0_DAT10/ECSPI2_MISO)* L20(SD1_DAT3)* L21(SD1_CLK)* M21(MCA_IO12)* N20(MCA_IO/USB0_P)* N21(MCA_IO13)* N22(MCA_IO07)* N24(SD1_DAT0)* P20(MCA_IO/USB0_N)* P21(MCA_IO14)* P22(MCA_IO08)* P23(MCA_IO01)* R2(ENET_RX_ER)* R20(MCA_IO19)* R21(MCA_IO16)* T20(MCA_IO24)* T21(MCA_IO22)* T22(MCA_IO10)* T24(MCA_IO03)* U2(ENET_TXD0)* U19(EIM_DA3)* U20(EIM_DA0)* U22(MCA_IO11)* V2(ENET_TXD1)* V19(EIM_DA9)* V24(EIM_DA2)* W22(EIM_DA8)* W23(EIM_DA1)* Y2(ENET_RXD0)* Y10(PMIC_GPIO14)* Y22(MCA_IO27)* Y23(MCA_IO23)*

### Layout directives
differential pair; net class DIFF100: CSI_CLK0_N, CSI_CLK0_P, CSI_D0_N, CSI_D0_P, CSI_D1_N, CSI_D1_P, DSI_CLK0_N, DSI_CLK0_P, DSI_D0_N, DSI_D0_P, DSI_D1_N, DSI_D1_P, HDMI_CLK_N, HDMI_CLK_P, HDMI_D0_N, HDMI_D0_P, HDMI_D1_N, HDMI_D1_P, HDMI_D2_N, HDMI_D2_P, LVDS0_CLK_N, LVDS0_CLK_P, LVDS0_TX0_N, LVDS0_TX0_P, LVDS0_TX1_N, LVDS0_TX1_P, LVDS0_TX2_N, LVDS0_TX2_P, LVDS0_TX3_N, LVDS0_TX3_P, LVDS1_CLK_N, LVDS1_CLK_P, LVDS1_TX0_N, LVDS1_TX0_P, LVDS1_TX1_N, LVDS1_TX1_P, LVDS1_TX2_N, LVDS1_TX2_P, LVDS1_TX3_N, LVDS1_TX3_P, SATA_RX_N, SATA_RX_P, SATA_TX_N, SATA_TX_P
differential pair; net class DIFF90: USB_OTG_D_N, USB_OTG_D_P, USBH_D_N, USBH_D_P
differential pair; net class DIFF85: CLK1_N, CLK1_P, PCIE_RX_N, PCIE_RX_P, PCIE_TX_N, PCIE_TX_P

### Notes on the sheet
- ConnectCore for i.MX6 Module
- DSI_RESET_N
- (near U1) DSI_CONTRAST
- (DSI_PWR_EN)
- (near U1) CSI_D2_P
- (near U1) CSI_D2_N
- (near U1) CSI_D3_P
- (near U1) CSI_D3_N

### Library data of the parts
R1-R3 = 1000466: RES 49.9 OHM 1/10W 1% 0402 SMD; Part_Type: Resistor; Manufacturer: Panasonic - ECG; Manufacturer_Part_Number: ERJ-2RKF49R9X; Component_Life_Cycle_State: CAD Reviewed; Area: 0.95; Project: KITT; Power_WV_SRF: 100; Digi_PN: 13051083
R4 R5 R20 R80-R82 = 1000076: RES 0.0 OHM 1/10W 0402 SMD; Part_Type: Resistor; Manufacturer: Panasonic - ECG; Manufacturer_Part_Number: ERJ-2GE0R00X; Component_Life_Cycle_State: Proven; Area: 0.95; Project: Adjustable Foundation; Power_WV_SRF: 10; Digi_PN: 13050387
R23 R153 = 1000537: RES 10.0K OHM 1/10W 1% 0402 SMD; Part_Type: Resistor; Manufacturer: Panasonic - ECG; Manufacturer_Part_Number: ERJ-2RKF1002X; Component_Life_Cycle_State: CAD Reviewed; Area: 0.95; Project: KITT; Power_WV_SRF: 100; Digi_PN: 13051084
R83 = 1000208: RES 0.0 OHM 1/10W 0603; Part_Type: Resistor; Manufacturer: Panasonic - ECG; Manufacturer_Part_Number: ERJ-3GEY0R00V; Note: 13051103 = Digi No. for GE WDNU; Digi_PN: 13050568; Component_Life_Cycle_State: Reviewed; Area: 2.5; Project: Adjustable Foundation; Voltage: 75V
TP1 TP2 = CAD0011: TEST POINT 30mil PAD SMT; Component_Life_Cycle_State: Reviewed; Area: 0.58; Project: CLC
U1 = 1001177: module, CCWMX6; Manufacturer: DIGI; Manufacturer_Part_Number: 50001876-02; Digi_PN: 50001475-02; Component_Life_Cycle_State: Reviewed; Area: 2500; Project: CCWMX6_SBC board

## Sheet 03 - Power, boot strap, reset.SchDoc: Power, Boot
size A3; PageSetup: Record=PageOptions¦CenterHorizontal=True¦CenterVertical=True¦PrintScale=0.70¦XCorrection=1.00¦YCorrection=1.00¦PrintKind=0¦BorderSize=5000000¦LeftOffset=0¦BottomOffset=0¦Orientation=2¦PaperLength=4200¦PaperWidth=2970¦Scale=100¦PaperSource=7¦PrintQuality=600¦MediaType=1¦DitherType=10¦PaperKind=A4¦PrintScaleMode=1; Author: Daniel Alesanco; SheetNumber: 3; SheetTotal: 13
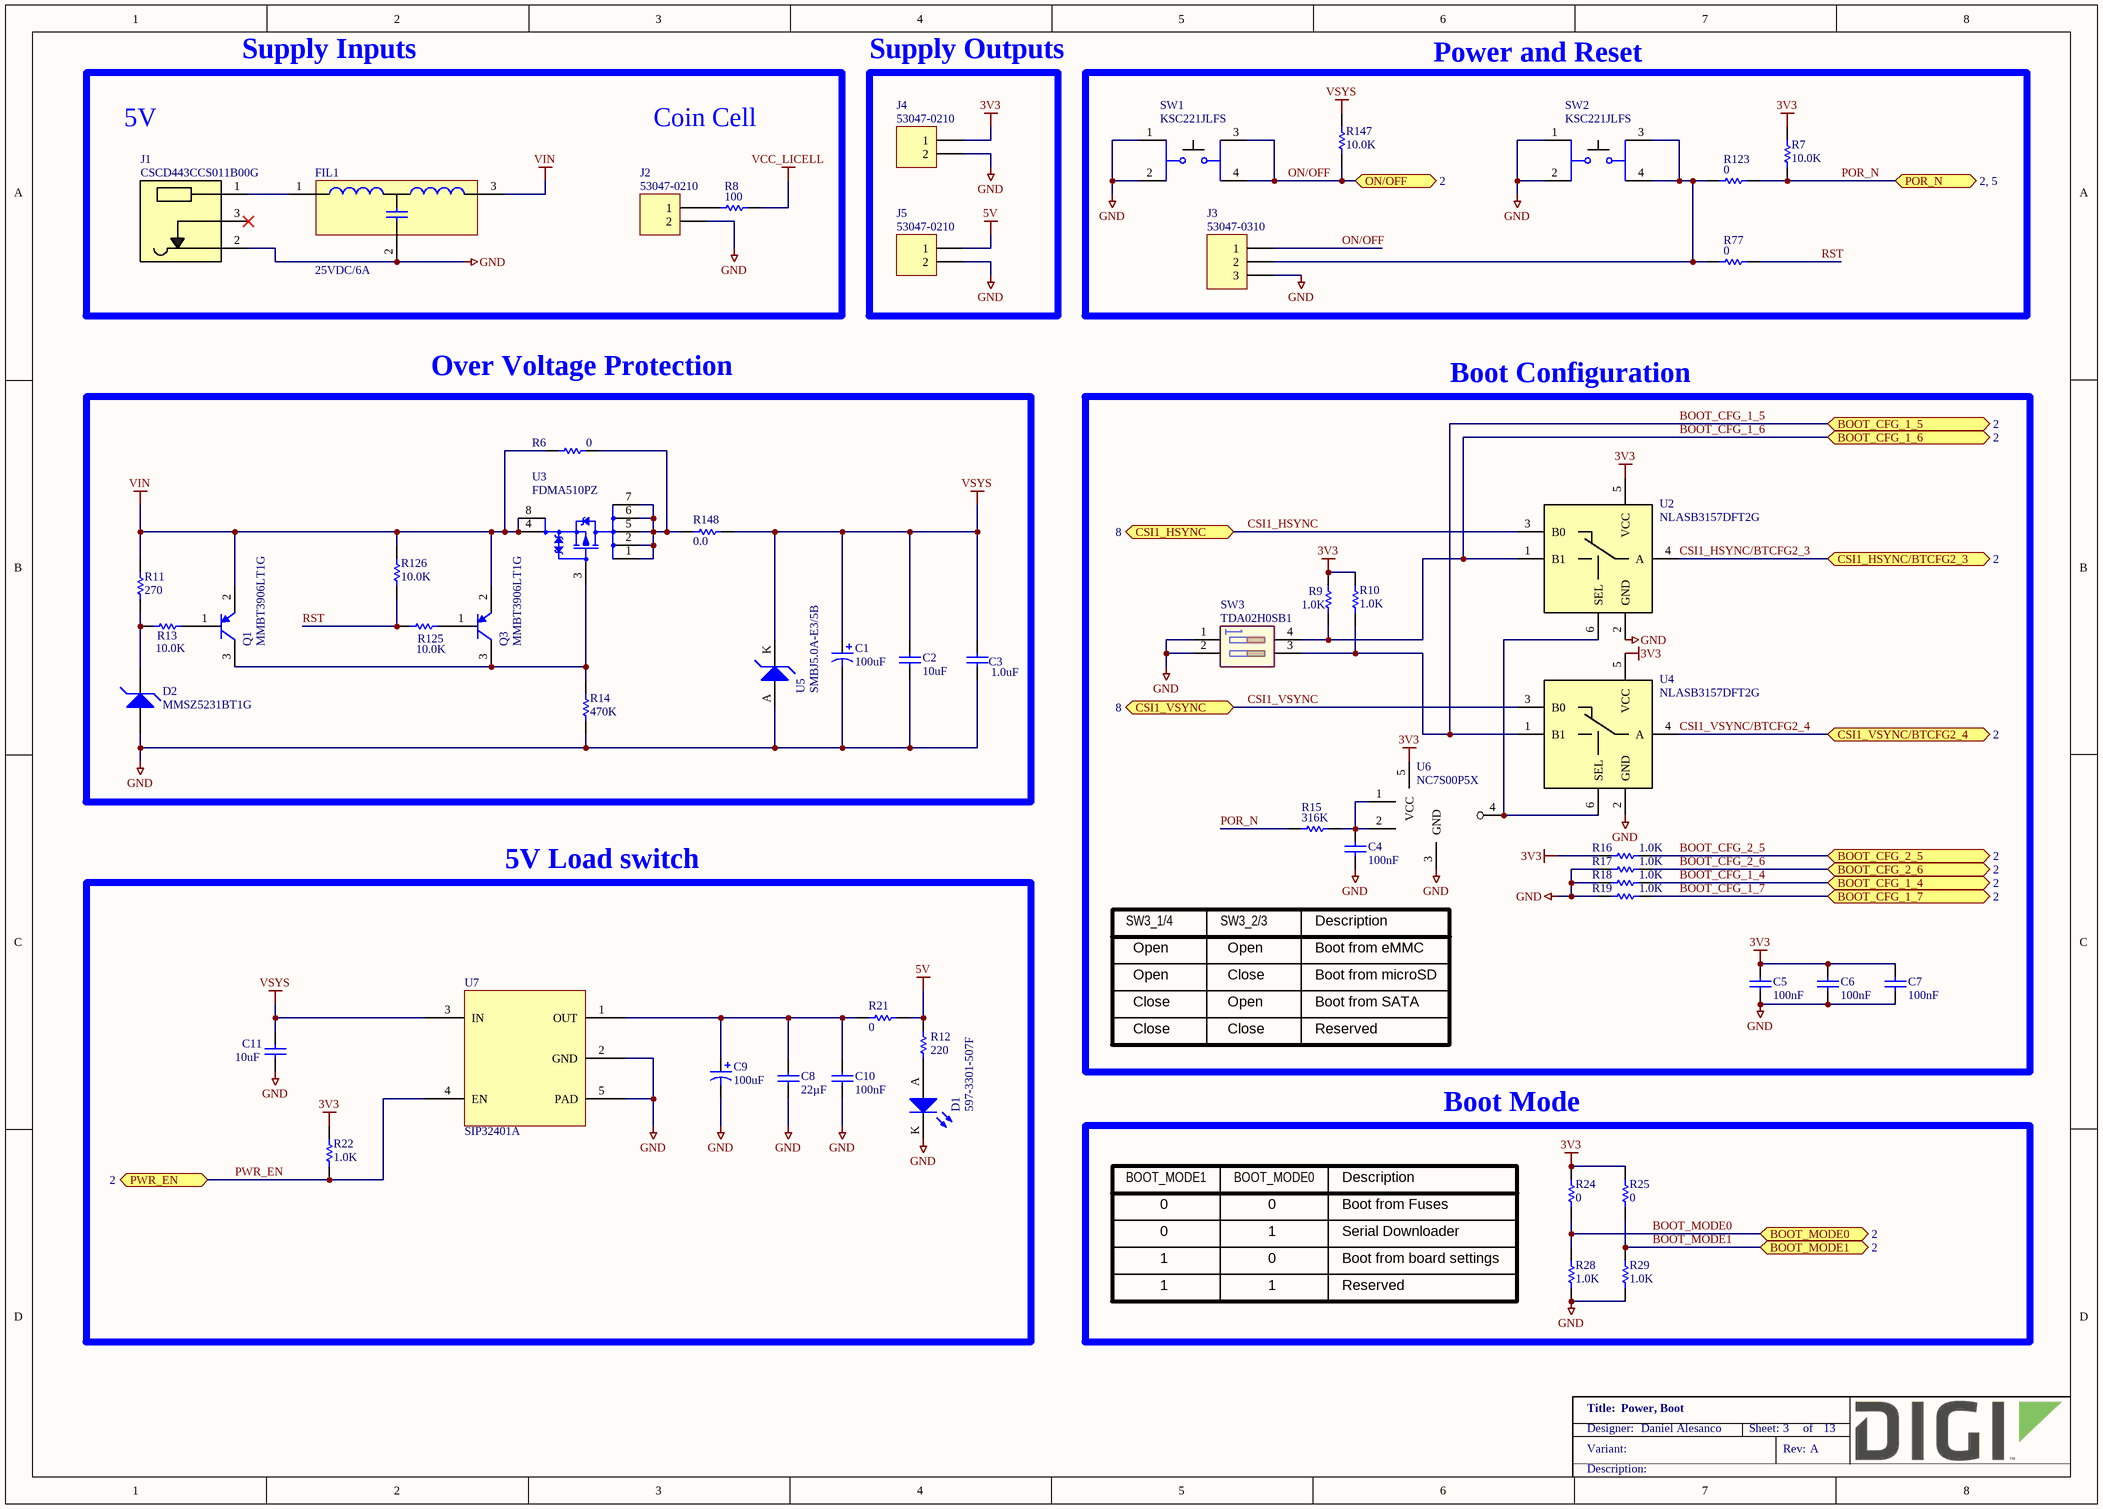
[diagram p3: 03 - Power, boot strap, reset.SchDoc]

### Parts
C1  100uF  [CAPMP3216X120N]
C2  10uF  [CAPC1005X55N]
C3  1.0uF  [CAPC1005X55N]
C4  100nF  [CAPC1005X55N]
C5  100nF  [CAPC1005X55N]
C6  100nF  [CAPC1005X55N]
C7  100nF  [CAPC1005X55N]
C8  22µF  [CAPC1608X90N]
C9  100uF  [CAPMP3216X120N]
C10  100nF  [CAPC1005X55N]
C11  10uF  [CAPC1005X55N]
D1  597-3301-507F  [LEDM3020X130N]
D2  MMSZ5231BT1G  [SOD3716X135N]
FIL1  25VDC/6A  [FIL_ELKEA]
J1  CSCD443CCS011B00G  [conn_CSCD443CCS011B00G]
J2  Manufacturer_Part_Number: 53047-0210  [MOLEX_53047-0210]  (hidden comment: 1x2P)
J3  Manufacturer_Part_Number: 53047-0310  [MOLEX_53047-0310]  (hidden comment: 1x3P)
J4  Manufacturer_Part_Number: 53047-0210  [MOLEX_53047-0210]  (hidden comment: 1x2P)
J5  Manufacturer_Part_Number: 53047-0210  [MOLEX_53047-0210]  (hidden comment: 1x2P)
Q1  MMBT3906LT1G  [SOT95P240X110-3N]
Q3  MMBT3906LT1G  [SOT95P240X110-3N]
R6  0  [RESC1005X40N]
R7  10.0K  [RESC1005X40N]
R8  100  [RESC1005X40N]
R9  1.0K  [RESC1005X40N]
R10  1.0K  [RESC1005X40N]
R11  270  [RESC2013X70N]
R12  220  [RESC1005X40N]
R13  10.0K  [RESC1005X40N]
R14  470K  [RESC1005X40N]
R15  316K  [RESC1609X55N]
R16  1.0K  [RESC1005X40N]
R17  1.0K  [RESC1005X40N]
R18  1.0K  [RESC1005X40N]
R19  1.0K  [RESC1005X40N]
R21  0  [RESC1609X55N]
R22  1.0K  [RESC1005X40N]
R24  0  [RESC1005X40N]
R25  0  [RESC1005X40N]
R28  1.0K  [RESC1005X40N]
R29  1.0K  [RESC1005X40N]
R77  0  [RESC1005X40N]
R123  0  [RESC1005X40N]
R125  10.0K  [RESC1005X40N]
R126  10.0K  [RESC1005X40N]
R147  10.0K  [RESC1005X40N]
R148  0.0  [RESC2013X70N]
SW1  KSC221JLFS  [SW_KSC221J]
SW2  KSC221JLFS  [SW_KSC221J]
SW3  TDA02H0SB1  [SW_TDA02]
U2  NLASB3157DFT2G  [SOT65P210X110-6N]
U3  FDMA510PZ  [DFN200X200X80-6N]
U4  NLASB3157DFT2G  [SOT65P210X110-6N]
U5  SMBJ5.0A-E3/5B  [DIOM5436X244N]
U6  NC7S00P5X  [SOT65P210X110-5N]
U7  SIP32401A  [SON50P120X160X60-5T55X91N]

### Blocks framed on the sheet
Supply Inputs: FIL1 J1 J2 R8
Supply Outputs: J4 J5
Power and Reset: J3 R7 R77 R123 R147 SW1 SW2
Over Voltage Protection: C1-C3 D2 Q1 Q3 R6 R11 R13 R14 R125 R126 R148 U3 U5
Boot Configuration: C4-C7 R9 R10 R15-R19 SW3 U2 U4 U6
5V Load switch: C8-C11 D1 R12 R21 R22 U7
Boot Mode: R24 R25 R28 R29

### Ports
BOOT_CFG_1_4 (bidir, see 2), BOOT_CFG_1_5 (bidir, see 2), BOOT_CFG_1_6 (bidir, see 2), BOOT_CFG_1_7 (bidir, see 2), BOOT_CFG_2_5 (bidir, see 2), BOOT_CFG_2_6 (bidir, see 2), BOOT_MODE0 (bidir, see 2), BOOT_MODE1 (bidir, see 2), CSI1_HSYNC (bidir, see 8), CSI1_HSYNC/BTCFG2_3 (bidir, see 2), CSI1_VSYNC (bidir, see 8), CSI1_VSYNC/BTCFG2_4 (bidir, see 2), ON/OFF (bidir, see 2), POR_N (bidir, see 2, 5), PWR_EN (bidir, see 2)

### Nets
3V3: C5.2 C6.2 C7.2 J4.1 R7.2 R9.2 R10.2 R16.2 R22.2 R24.2 R25.2 U2.5(VCC) U4.5(VCC) U6.5(VCC)
5V: J5.1 R12.2 R21.2
GND: C1.2 C2.1 C3.1 C4.1 C5.1 C6.1 C7.1 C8.1 C9.2 C10.1 C11.1 D1.K D2.A FIL1.2 J1.2 J2.2 J3.3 J4.2 J5.2 R14.1 R17.2 R18.2 R19.2 R28.2 R29.2 SW1.1 SW1.2 SW2.1 SW2.2 SW3.1(A1) SW3.2(A2) U2.2(GND) U4.2(GND) U5.A U6.3(GND) U7.2(GND) U7.5(PAD)
VCC_LICELL: R8.2
VIN: FIL1.3(GND) Q1.2(E) Q3.2(E) R6.1 R11.2 R126.2 U3.4(S) U3.8(S)
VSYS: C1.1 C2.2 C3.2 C11.2 R147.2 R148.2 U5.K U7.3(IN)
BOOT_CFG_1_4: R18.1 ; port BOOT_CFG_1_4
BOOT_CFG_1_5: R10.1 SW3.3(B2) U4.1(B1) ; port BOOT_CFG_1_5
BOOT_CFG_1_6: R9.1 SW3.4(B1) U2.1(B1) ; port BOOT_CFG_1_6
BOOT_CFG_1_7: R19.1 ; port BOOT_CFG_1_7
BOOT_CFG_2_5: R16.1 ; port BOOT_CFG_2_5
BOOT_CFG_2_6: R17.1 ; port BOOT_CFG_2_6
BOOT_MODE0: R24.1 R28.1 ; port BOOT_MODE0
BOOT_MODE1: R25.1 R29.1 ; port BOOT_MODE1
CSI1_HSYNC: U2.3(B0) ; port CSI1_HSYNC
CSI1_HSYNC/BTCFG2_3: U2.4(A) ; port CSI1_HSYNC/BTCFG2_3
CSI1_VSYNC: U4.3(B0) ; port CSI1_VSYNC
CSI1_VSYNC/BTCFG2_4: U4.4(A) ; port CSI1_VSYNC/BTCFG2_4
ON/OFF: J3.1 R147.1 SW1.3 SW1.4 ; port ON/OFF
POR_N: R7.1 R15.1 R123.2 ; port POR_N
PWR_EN: R22.1 U7.4(EN) ; port PWR_EN
RST: R77.2 R125.1 R126.1
NetC4_2: C4.2 R15.2 U6.1(A) U6.2(B)
NetC8_2: C8.2 C9.1 C10.2 R21.1 U7.1(OUT)
NetD1_A: D1.A R12.1
NetD2_K: D2.K R11.1 R13.1
NetFIL1_1: FIL1.1(GND) J1.1
NetJ2_1: J2.1 R8.1
NetJ3_2: J3.2 R77.1 R123.1 SW2.3 SW2.4
NetQ1_1: Q1.1(B) R13.2
NetQ1_3: Q1.3(C) Q3.3(C) R14.2 U3.3(G)
NetQ3_1: Q3.1(B) R125.2
NetR6_2: R6.2 R148.1 U3.1(D) U3.2(D) U3.5(D) U3.6(D) U3.7(D)
NetU2_6: U2.6(SEL) U4.6(SEL) U6.4(Y)

Not connected (* = marked no-connect by the designer): J1 3*

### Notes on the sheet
- 5V
- Coin Cell
- SW3_1/4
- Open
- SW3_2/3
- Close
- Description
- Boot from eMMC
- Boot from microSD
- Boot from SATA
- Reserved
- BOOT_MODE1
- BOOT_MODE0
- 0
- 1
- Boot from Fuses
- Serial Downloader
- Boot from board settings

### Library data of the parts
C1 C9 = 1001196: CAP TANT 100UF 6.3V 20% 1206; Part_Type: Capacitor; Manufacturer: Rohm; Manufacturer_Part_Number: TCTAL0J107M8R; Digi_PN: 14050490; Component_Life_Cycle_State: Reviewed; Area: 8.01; Project: CCWMX6_SBC board
C2 C11 = 1001168: CAP CER 10UF 10V 20% X5R 0402; Part_Type: Capacitor; Manufacturer: Samsung; Manufacturer_Part_Number: CL05A106MP5NUNC; Digi_PN: 14050689; Component_Life_Cycle_State: Reviewed; Area: 0.95; Project: CCWMX6_SBC board
C3 = 1001167: CAP CER 1UF 10V 10% X5R 0402; Part_Type: Capacitor; Manufacturer: Murata; Manufacturer_Part_Number: GRM155R61A105KE15D; Digi_PN: 14050399; Component_Life_Cycle_State: Reviewed; Area: 0.95; Project: CCWMX6_SBC board
C4-C7 C10 = 1000006: CAP 100nF 16V 10% X7R 0402; Part_Type: Capacitor; Manufacturer: Murata; Manufacturer_Part_Number: GRM155R71C104KA88D; Component_Life_Cycle_State: CAD Reviewed; Area: 0.95; Project: KITT; Tolerance: 10; Digi_PN: 14050552
C8 = 1000998: CAP CER 22UF 10V 20% X5R 0603; Part_Type: Capacitor; Manufacturer: Samsung; Manufacturer_Part_Number: CL10A226MP8NUNE; Manufacturer_Alt_1: TDK Corporation; Manufacturer_Alt_1_Part_Number: C1608X5R1A226M080AC; Digi_PN: 14050684; Component_Life_Cycle_State: Reviewed; Area: 2.27; Project: ConnectCore i.MX6 module; Tolerance: 20
D1 = 1001189: LED GREEN 573NM 1208 SMD; Manufacturer: Dialight; Digi_PN: 17050183; Component_Life_Cycle_State: Reviewed; Area: 6; Project: CCWMX6_SBC board; Note: 17050846 = Digi PN for GE WDNU II
D2 = 1001494: DIODE ZENER 5.1V 500MW SOD123; Part_Type: Diodes; Manufacturer: On Semiconductor; Digi_PN: 17050700; Component_Life_Cycle_State: Reviewed; Area: 8.28; Project: CCWMX6_SBC board; Note: 17050805 = Digi No. for GE WDNU
FIL1 = 1001918: DNF 2 MHZ -1000 MHZ SMD; Part_Type: Filter; Manufacturer: Panasonic - ECG; Manufacturer_Part_Number: ELKEA333FA; Digi_PN: 21000532; Component_Life_Cycle_State: Created; Area: 5.76; Project: CCWMX6_SBC board
J1 = 1001105: DC Power Jack; Part_Type: Connector; Manufacturer: Bobbintron Electrical Corp; Digi_PN: 18000302; Component_Life_Cycle_State: Reviewed; Area: 137; Project: CCWMX6_SBC board
J2 J4 J5 = 1001136: CONN HEADER 2POS 1.25MM VERT TIN; Part_Type: Connector; Manufacturer: Molex; Component_Life_Cycle_State: Reviewed; Area: 13.6; Project: CCWMX6_SBC board; Digi_PN: 18050343
J3 = 1001183: CONN HEADER 3POS 1.25MM VERT TIN; Part_Type: Connector; Manufacturer: Molex; Digi_PN: 18050349; Component_Life_Cycle_State: Reviewed; Area: 17.6; Project: CCWMX6_SBC board
Q1 Q3 = 1001204: TRANS GP SS PNP 40V SOT23; Part_Type: IC; Manufacturer: On Semiconductor; Digi_PN: 17050145; Component_Life_Cycle_State: Reviewed; Area: 10.92; Project: CCWMX6_SBC board
R6 R24 R25 R77 R123 = 1000076: as R4 on sheet 02 - CCIMX6 Module
R7 R147 = 1000537: as R23 on sheet 02 - CCIMX6 Module
R8 = 1000467: RES 100 OHM 1/10W 1% 0402 SMD; Part_Type: Resistor; Manufacturer: Panasonic - ECG; Manufacturer_Part_Number: ERJ-2RKF1000X; Component_Life_Cycle_State: CAD Reviewed; Area: 0.95; Project: KITT; Digi_PN: 13051087
R9 R10 R16-R19 R22 R28 R29 = 1000079: RES 1.00K OHM 1/10W 1% 0402 SMD; Part_Type: Resistor; Manufacturer: Panasonic - ECG; Manufacturer_Part_Number: ERJ-2RKF1001X; Digi_PN: 13051085; Component_Life_Cycle_State: Proven; Area: 0.95; Project: Adjustable Foundation; Power_WV_SRF: 10
R11 = 1001323: RES 270 OHM 1/2W 5% 0805 SMD; Part_Type: Resistor; Manufacturer: Panasonic - ECG; Manufacturer_Part_Number: ERJ-P06J271V; Digi_PN: 13051049; Component_Life_Cycle_State: Reviewed; Area: 4.12; Project: Pinnacle; Power_WV_SRF: 500
R12 = 1001154: RES 220 OHM 1/16W 1% 0402 SMD; Part_Type: Resistor; Manufacturer: Yageo; Manufacturer_Part_Number: RC0402FR-07220RL; Digi_PN: 13050623; Component_Life_Cycle_State: Reviewed; Area: 0.95; Project: CCWMX6_SBC board
R13 R125 R126 = 1000537: RES 10.0K OHM 1/10W 1% 0402 SMD; Part_Type: Resistor; Manufacturer: Panasonic - ECG; Manufacturer_Part_Number: ERJ-2RKF1002X; Digi_PN: 13051084; Component_Life_Cycle_State: CAD Reviewed; Area: 0.95; Project: KITT; Power_WV_SRF: 100
R14 = 1000701: RES 470K OHM 1/10W 1% 0402 SMD; Part_Type: Resistor; Manufacturer: Panasonic - ECG; Manufacturer_Part_Number: ERJ-2RKF4703X; Component_Life_Cycle_State: CAD Reviewed; Area: 0.95; Project: KITT; Power_WV_SRF: 100; Digi_PN: 13051092
R15 = 1001150: RES 316K OHM 1/10W 1% 0603 SMD; Part_Type: Resistor; Manufacturer: Yageo; Manufacturer_Part_Number: RC0603FR-07316KL; Digi_PN: 13050512; Component_Life_Cycle_State: Reviewed; Area: 1.5; Project: CCWMX6_SBC board; Power_WV_SRF: 100
R21 = 1000208: as R83 on sheet 02 - CCIMX6 Module
R148 = 1001557: RES 0.0 OHM 1/8W JUMP 0805 SMD; Part_Type: Resistor; Manufacturer: Yageo; Manufacturer_Part_Number: RC0805JR-070RL; Note: 13051095 = Digi No. for GE WDNU; Digi_PN: TR00037; Component_Life_Cycle_State: Reviewed; Area: 5.8; Project: WDNU-II; Power_WV_SRF: 125
SW1 SW2 = 1001124: SWITCH TACTILE SPST-NO 0.05A 32V; Manufacturer: ITT; Digi_PN: 22000059; Component_Life_Cycle_State: Reviewed; Area: 37; Project: CCWMX6_SBC board; Note: 22000295 = Digi No. for GE WDNU
SW3 = 1001500: SWITCH DIP 2POS HALF PITCH 24V; Manufacturer: C&K Components; Digi_PN: 22000060; Component_Life_Cycle_State: Reviewed; Area: 34.3; Project: CCWMX6_SBC board; Note: 22000296 = Digi No. for GE WDNU
U2 U4 = 1001179: IC SWITCH SPDT SC88; Manufacturer: On Semiconductor; Digi_PN: 16051954; Component_Life_Cycle_State: Reviewed; Project: CCWMX6_SBC board; Area: 4.8
U3 = 1001205: MOSFET P-CH 20V 7.8A 6-MICROFET; Part_Type: IC; Manufacturer: Fairchild Semiconductor; Digi_PN: 17050636; Component_Life_Cycle_State: Reviewed; Area: 4; Project: CCWMX6_SBC board
U5 = 1001206: TVS DIODE 5VWM 9.2VC SMB; Part_Type: Circuit Protection; Manufacturer: Vishay Semiconductors; Digi_PN: 17050018; Component_Life_Cycle_State: Reviewed; Area: 22.4; Project: CCWMX6_SBC board
U6 = 1001160: IC GATE NAND 2-INP HS LOG SC70-5; Manufacturer: Fairchild Semiconductor; Digi_PN: 16050675; Component_Life_Cycle_State: Reviewed; Area: 6.93; Project: CCWMX6_SBC board
U7 = 1001857: IC SW W/CTRL SLEW RATE 4TDFN; Manufacturer: Vishay Siliconix; Manufacturer_Part_Number: SIP32401ADNP-T1GE4; Component_Life_Cycle_State: Reviewed; Area: 4.93; Project: CCWMX6_SBC board; Digi_PN: 16052004

## Sheet 04 - SATA, microSD, Mini PCIe, microSIM.SchDoc: SATA, MicroSD, Mini PCIe, MicroSIM
size A3; PageSetup: Record=PageOptions¦CenterHorizontal=True¦CenterVertical=True¦PrintScale=0.70¦XCorrection=1.00¦YCorrection=1.00¦PrintKind=0¦BorderSize=5000000¦LeftOffset=0¦BottomOffset=0¦Orientation=2¦PaperLength=4200¦PaperWidth=2970¦Scale=100¦PaperSource=7¦PrintQuality=600¦MediaType=1¦DitherType=10¦PaperKind=A4¦PrintScaleMode=1; Author: Daniel Alesanco; SheetNumber: 4; SheetTotal: 13
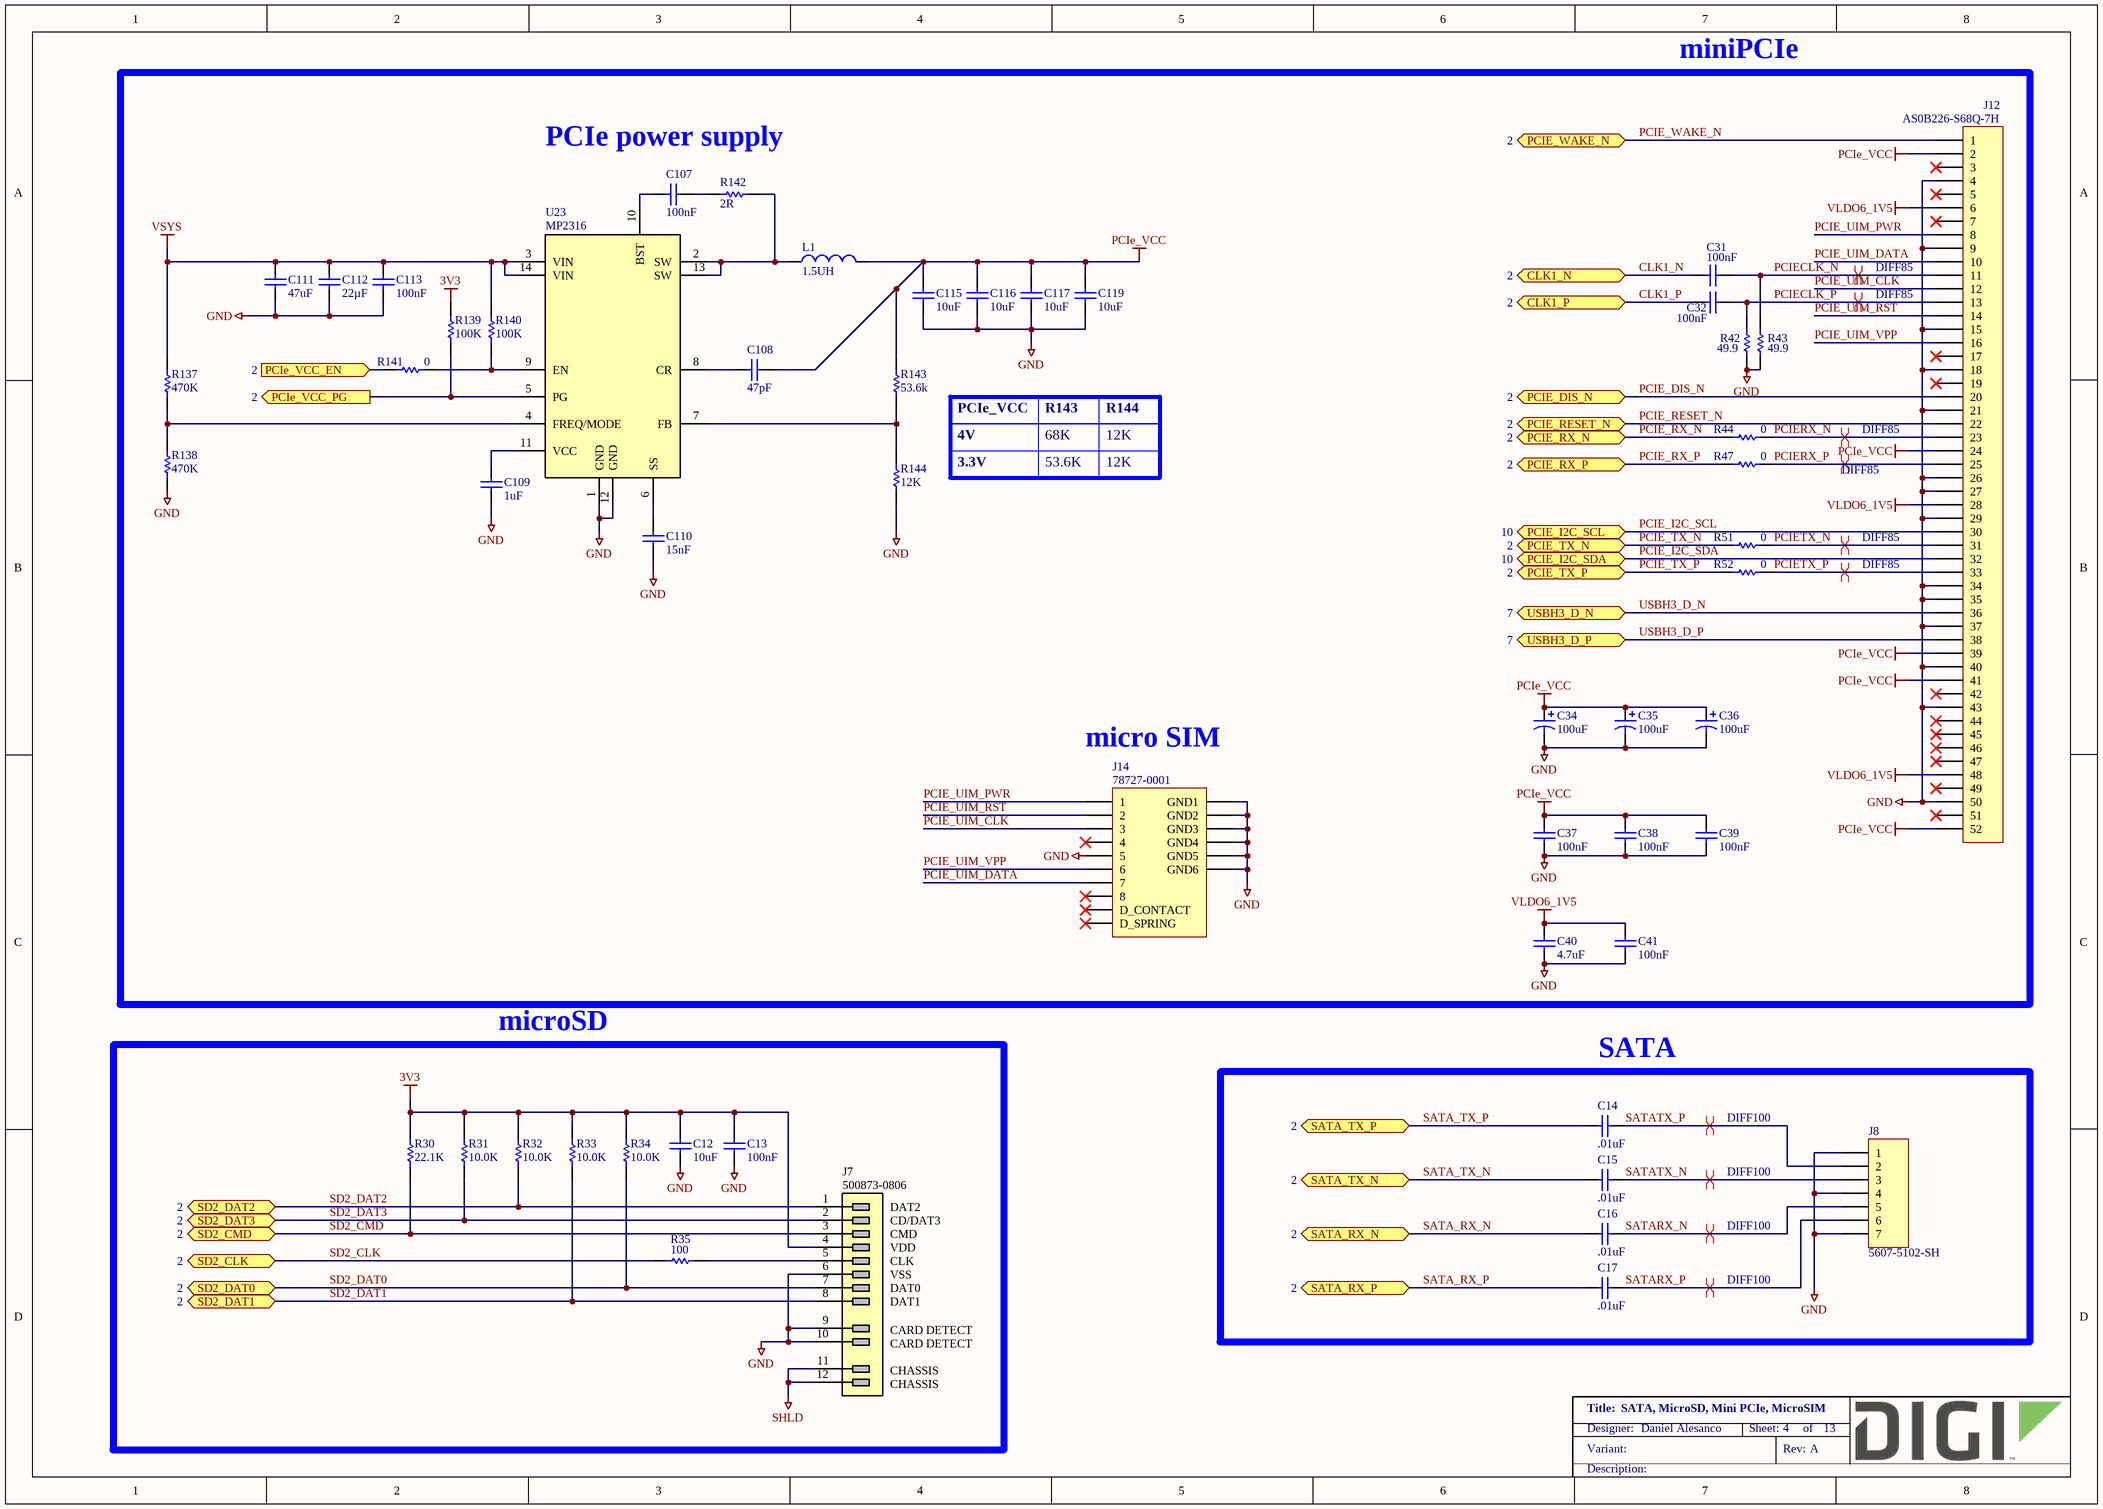
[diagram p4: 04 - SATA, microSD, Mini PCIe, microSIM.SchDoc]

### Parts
C12  10uF  [CAPC1005X55N]
C13  100nF  [CAPC1005X55N]
C14  .01uF  [CAPC1005X55N]
C15  .01uF  [CAPC1005X55N]
C16  .01uF  [CAPC1005X55N]
C17  .01uF  [CAPC1005X55N]
C31  100nF  [CAPC1005X55N]
C32  100nF  [CAPC1005X55N]
C34  100uF  [CAPMP3216X120N]
C35  100uF  [CAPMP3216X120N]
C36  100uF  [CAPMP3216X120N]
C37  100nF  [CAPC1005X55N]
C38  100nF  [CAPC1005X55N]
C39  100nF  [CAPC1005X55N]
C40  4.7uF  [CAPC2013X135N]
C41  100nF  [CAPC1005X55N]
C107  100nF  [CAPC1005X55N]
C108  47pF  [CAPC1005X55N]
C109  1uF  [CAPC1608X90N]
C110  15nF  [CAPC1005X55N]
C111  47uF  [CAPC2013X145N]
C112  22µF  [CAPC1608X90N]
C113  100nF  [CAPC1005X55N]
C115  10uF  [CAPC2013X135N]
C116  10uF  [CAPC2013X135N]
C117  10uF  [CAPC2013X135N]
C119  10uF  [CAPC2013X135N]
J7  500873-0806  [MOLEX_500873-0806]
J8  5607-5102-SH  [3M_5607-5102-SH]
J12  Manufacturer_Part_Number: AS0B226-S68Q-7H  [FOXCONN_AS0B221-S68Q-7H]  (hidden comment: PCIe Minicard)
J14  78727-0001  [MOLEX_78727-0001]
L1  1.5UH  [INDM_SRP4020TA]
R30  22.1K  [RESC1005X40N]
R31  10.0K  [RESC1005X40N]
R32  10.0K  [RESC1005X40N]
R33  10.0K  [RESC1005X40N]
R34  10.0K  [RESC1005X40N]
R35  100  [RESC1005X40N]
R42  49.9  [RESC1005X40N]
R43  49.9  [RESC1005X40N]
R44  0  [RESC1005X40N]
R47  0  [RESC1005X40N]
R51  0  [RESC1005X40N]
R52  0  [RESC1005X40N]
R137  470K  [RESC1005X40N]
R138  470K  [RESC1005X40N]
R139  100K  [RESC1005X40N]
R140  100K  [RESC1005X40N]
R141  0  [RESC1005X40N]
R142  2R  [RESC1609X55N]
R143  53.6k  [RESC1609X55N]
R144  12K  [RESC1609X55N]
U23  MP2316  [QFN_MPS_MP2316]

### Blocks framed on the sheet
microSD: C12 C13 J7 R30-R35
SATA: C14-C17 J8

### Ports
CLK1_N (bidir, see 2), CLK1_P (bidir, see 2), PCIE_DIS_N (bidir, see 2), PCIE_I2C_SCL (bidir, see 10), PCIE_I2C_SDA (bidir, see 10), PCIE_RESET_N (bidir, see 2), PCIE_RX_N (bidir, see 2), PCIE_RX_P (bidir, see 2), PCIE_TX_N (bidir, see 2), PCIE_TX_P (bidir, see 2), PCIe_VCC_EN (in, see 2), PCIe_VCC_PG (out, see 2), PCIE_WAKE_N (bidir, see 2), SATA_RX_N (bidir, see 2), SATA_RX_P (bidir, see 2), SATA_TX_N (bidir, see 2), SATA_TX_P (bidir, see 2), SD2_CLK (bidir, see 2), SD2_CMD (bidir, see 2), SD2_DAT0 (bidir, see 2), SD2_DAT1 (bidir, see 2), SD2_DAT2 (bidir, see 2), SD2_DAT3 (bidir, see 2), USBH3_D_N (bidir, see 7), USBH3_D_P (bidir, see 7)

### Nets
3V3: C12.2 C13.2 J7.4 R30.2 R31.2 R32.2 R33.2 R34.2 R139.1
GND: C12.1 C13.1 C34.2 C35.2 C36.2 C37.1 C38.1 C39.1 C40.1 C41.1 C109.1 C110.1 C111.1 C112.1 C113.1 C115.1 C116.1 C117.1 C119.1 J7.6 J7.9 J7.10 J8.1 J8.4 J8.7 J12.4 J12.9 J12.15 J12.18 J12.21 J12.26 J12.27 J12.29 J12.34 J12.35 J12.37 J12.40 J12.43 J12.50 J14.5 J14.11(GND1) J14.12(GND2) J14.13(GND3) J14.14(GND4) J14.15(GND5) J14.16(GND6) R42.1 R43.1 R138.1 R144.1 U23.1(GND) U23.12(GND)
PCIe_VCC: C34.1 C35.1 C36.1 C37.2 C38.2 C39.2 C108.2 C115.2 C116.2 C117.2 C119.2 J12.2 J12.24 J12.39 J12.41 J12.52 L1.2 R143.2
SHLD: J7.11 J7.12
VLDO6_1V5: C40.2 C41.2 J12.6 J12.28 J12.48
VSYS: C111.2 C112.2 C113.2 R137.2 R140.2 U23.3(VIN) U23.14(VIN)
CLK1_N: C31.1 ; port CLK1_N
CLK1_P: C32.1 ; port CLK1_P
PCIE_DIS_N: J12.20 ; port PCIE_DIS_N
PCIE_I2C_SCL: J12.30 ; port PCIE_I2C_SCL
PCIE_I2C_SDA: J12.32 ; port PCIE_I2C_SDA
PCIE_RESET_N: J12.22 ; port PCIE_RESET_N
PCIE_RX_N: R44.1 ; port PCIE_RX_N
PCIE_RX_P: R47.1 ; port PCIE_RX_P
PCIE_TX_N: R51.1 ; port PCIE_TX_N
PCIE_TX_P: R52.1 ; port PCIE_TX_P
PCIE_UIM_CLK: J12.12 J14.3
PCIE_UIM_DATA: J12.10 J14.7
PCIE_UIM_PWR: J12.8 J14.1
PCIE_UIM_RST: J12.14 J14.2
PCIE_UIM_VPP: J12.16 J14.6
PCIe_VCC_EN: R141.1 ; port PCIe_VCC_EN
PCIe_VCC_PG: R139.2 U23.5(PG) ; port PCIe_VCC_PG
PCIE_WAKE_N: J12.1 ; port PCIE_WAKE_N
PCIECLK_N: C31.2 J12.11 R43.2
PCIECLK_P: C32.2 J12.13 R42.2
PCIERX_N: J12.23 R44.2
PCIERX_P: J12.25 R47.2
PCIETX_N: J12.31 R51.2
PCIETX_P: J12.33 R52.2
SATA_RX_N: C16.1 ; port SATA_RX_N
SATA_RX_P: C17.1 ; port SATA_RX_P
SATA_TX_N: C15.1 ; port SATA_TX_N
SATA_TX_P: C14.1 ; port SATA_TX_P
SATARX_N: C16.2 J8.5
SATARX_P: C17.2 J8.6
SATATX_N: C15.2 J8.3
SATATX_P: C14.2 J8.2
SD2_CLK: R35.1 ; port SD2_CLK
SD2_CMD: J7.3 R30.1 ; port SD2_CMD
SD2_DAT0: J7.7 R34.1 ; port SD2_DAT0
SD2_DAT1: J7.8 R33.1 ; port SD2_DAT1
SD2_DAT2: J7.1 R32.1 ; port SD2_DAT2
SD2_DAT3: J7.2 R31.1 ; port SD2_DAT3
USBH3_D_N: J12.36 ; port USBH3_D_N
USBH3_D_P: J12.38 ; port USBH3_D_P
NetC107_1: C107.1 U23.10(BST)
NetC107_2: C107.2 R142.1
NetC108_1: C108.1 U23.8(CR)
NetC109_2: C109.2 U23.11(VCC)
NetC110_2: C110.2 U23.6(SS)
NetJ7_5: J7.5 R35.2
NetL1_1: L1.1 R142.2 U23.2(SW) U23.13(SW)
NetR137_1: R137.1 R138.2 U23.4(FREQ/MODE)
NetR140_1: R140.1 R141.2 U23.9(EN)
NetR143_1: R143.1 R144.2 U23.7(FB)

Not connected (* = marked no-connect by the designer): J12 3* 5* 7* 17* 19* 42* 44* 45* 46* 47* 49* 51*; J14 4* 8* 9(D_CONTACT)* 10(D_SPRING)*

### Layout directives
differential pair; net class DIFF100: SATARX_N, SATARX_P, SATATX_N, SATATX_P
differential pair; net class DIFF85: PCIECLK_N, PCIECLK_P, PCIERX_N, PCIERX_P, PCIETX_N, PCIETX_P

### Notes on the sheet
- miniPCIe
- PCIe power supply
- PCIe_VCC
- 4V
- R143
- 68K
- R144
- 12K
- 3.3V
- 53.6K
- (near J14) micro SIM

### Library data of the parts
C12 = 1001168: as C2 on sheet 03 - Power, boot strap, reset
C13 C31 C32 C37-C39 C41 = 1000006: as C4 on sheet 03 - Power, boot strap, reset
C14-C17 = 1001165: CAP CER 10000PF 16V 10% X7R 0402; Part_Type: Capacitor; Manufacturer: Kemet; Manufacturer_Part_Number: C0402C103K4RACTU; Digi_PN: 14050248; Component_Life_Cycle_State: Reviewed; Area: 0.95; Project: CCWMX6_SBC board
C34-C36 = 1001196: as C1 on sheet 03 - Power, boot strap, reset
C40 = 1000500: CAP CER 4.7UF 25V 10% X5R 0805; Part_Type: Capacitor; Manufacturer: Murata; Manufacturer_Part_Number: GRM21BR61E475KA12L; Component_Life_Cycle_State: Reviewed; Area: 4.24; Project: SDR Prototype RF Board; Digi_PN: 14050307
C107 = 1000006: CAP 100nF 16V 10% X7R 0402; Part_Type: Capacitor; Manufacturer: Murata; Manufacturer_Part_Number: GRM155R71C104KA88D; Digi_PN: 14050552; Component_Life_Cycle_State: CAD Reviewed; Area: 0.95; Project: KITT; Tolerance: 10
C108 = 1000007: CAP 47pF 50V 5% NP0 0402; Part_Type: Capacitor; Manufacturer: Murata; Manufacturer_Part_Number: GRM1555C1H470JA01D; Manufacturer_Alt_1: AVX Corporation; Manufacturer_Alt_1_Part_Number: 04025A470JAT2A; Note: 14050747 is Digi No. for GE WDNU; Digi_PN: 14050309; Component_Life_Cycle_State: CAD Reviewed; Area: 0.95; Project: KITT; Temp_Coef: C0G, NP0
C109 = 1000110: CAP CER 1UF 25V 10% X5R 0603; Part_Type: Capacitor; Manufacturer: Murata; Manufacturer_Part_Number: GRM188R61E105KA12D; Manufacturer_Alt_1: AVX Corporation; Manufacturer_Alt_1_Part_Number: TMK107BJ105KA-T; Note: 14050758  = Digi No. for GE WDNU; Digi_PN: 14050618; Component_Life_Cycle_State: Reviewed; Area: 2.27; Project: Adjustable Foundation
C110 = 1000512: CAP CER 0.015UF 16V 10% X7R 0402; Part_Type: Capacitor; Manufacturer: Murata; Manufacturer_Part_Number: GRM155R71C153KA01D; Digi_PN: 14050713; Component_Life_Cycle_State: CAD Reviewed; Area: 0.95; Project: Cellular Proof of Concept
C111 = 1000501: CAP CER 47UF 6.3V 20% X5R 0805; Part_Type: Capacitor; Manufacturer: Taiyo Yuden; Manufacturer_Part_Number: JMK212BJ476MG-T; Digi_PN: 14050627; Component_Life_Cycle_State: Reviewed; Area: 6.4; Project: SDR Prototype RF Board
C112 = 1000998: as C8 on sheet 03 - Power, boot strap, reset
C113 = 1000918: CAP CER 0.1UF 50V 10% X7R 0402; Part_Type: Capacitor; Manufacturer: TDK Corporation; Manufacturer_Part_Number: C1005X7R1H104K050BB; Digi_PN: 14050715; Component_Life_Cycle_State: Reviewed; Area: 0.95; Project: DTM3.0
C115-C117 C119 = 1000111: CAP CER 10UF 16V 10% X5R 0805; Part_Type: Capacitor; Manufacturer: Murata; Manufacturer_Part_Number: GRM21BR61C106KE15L; Digi_PN: 14050701; Component_Life_Cycle_State: Proven; Area: 3.99; Project: Adjustable Foundation; Tolerance: 10
J7 = 1001118: CONN TRANSFLSH R/A PUSH-PUSH SMD; Part_Type: Connector; Manufacturer: Molex; Digi_PN: MB03015; Component_Life_Cycle_State: Reviewed; Area: 213; Project: CCWMX6_SBC board
J8 = 1001115: CONN PLUG SATA 7PS VERT PCB GOLD; Part_Type: Connector; Manufacturer: 3M; Digi_PN: 18000550; Component_Life_Cycle_State: Reviewed; Area: 102; Project: CCWMX6_SBC board
J12 = 1001130: SMCONN,MINI PCI EXP, 6.8MM HT; Part_Type: Connector; Manufacturer: Foxconn; Digi_PN: 18000349; Component_Life_Cycle_State: Reviewed; Area: 150; Project: CCWMX6_SBC board
J14 = 1001120: MEMORY CARD 6POS PUSH/PULL SMD; Part_Type: Connector; Manufacturer: Molex; Digi_PN: 18000638; Component_Life_Cycle_State: Reviewed; Area: 217; Project: CCWMX6_SBC board
L1 = 1001912: FIXED IND 1.5UH 4.5A 42 MOHM SMD; Manufacturer: Bourns; Manufacturer_Part_Number: SRP4020TA-1R5M; Digi_PN: 21000530; Component_Life_Cycle_State: Created; Area: 18.067; Project: CCWMX6_SBC board
R30 = 1001149: RES 22.1K OHM 1/16W 1% 0402 SMD; Part_Type: Resistor; Manufacturer: Vishay Dale; Manufacturer_Part_Number: CRCW040222K1FKED; Digi_PN: 13050450; Component_Life_Cycle_State: Reviewed; Area: 0.95; Project: CCWMX6_SBC board; Power_WV_SRF: 0.063; Tolerance: ±100ppm/°C
R31-R34 = 1000537: as R23 on sheet 02 - CCIMX6 Module
R35 = 1000467: as R8 on sheet 03 - Power, boot strap, reset
R42 R43 = 1000466: as R1 on sheet 02 - CCIMX6 Module
R44 R47 R51 R52 R141 = 1000076: as R4 on sheet 02 - CCIMX6 Module
R137 R138 = 1000701: RES 470K OHM 1/10W 1% 0402 SMD; Part_Type: Resistor; Manufacturer: Panasonic - ECG; Manufacturer_Part_Number: ERJ-2RKF4703X; Digi_PN: 13051092; Component_Life_Cycle_State: CAD Reviewed; Area: 0.95; Project: KITT; Power_WV_SRF: 100
R139 R140 = 1000480: RES 100K OHM 1/10W 1% 0402 SMD; Part_Type: Resistor; Manufacturer: Panasonic - ECG; Manufacturer_Part_Number: ERJ-2RKF1003X; Digi_PN: 13051063; Component_Life_Cycle_State: CAD Reviewed; Area: 0.95; Project: KITT; Power_WV_SRF: 100
R142 = 1001916: RES SMD 2 OHM 5% 1/10W 0603; Part_Type: Resistor; Manufacturer: Panasonic - ECG; Manufacturer_Part_Number: ERJ-3GEYJ2R0V; Digi_PN: 13050488; Component_Life_Cycle_State: Created; Area: 1.28; Project: CCWMX6_SBC board; Power_WV_SRF: 100; Tolerance: 1
R143 = 1001518: RES 53.6K OHM 1/10W 1% 0603 SMD; Part_Type: Resistor; Manufacturer: Panasonic - ECG; Manufacturer_Part_Number: ERJ-3EKF5362V; Digi_PN: 13051064; Component_Life_Cycle_State: Reviewed; Area: 2.5; Project: WDNU-II
R144 = 1001200: RES 12.0K OHM 1/10W 1% 0603 SMD; Part_Type: Resistor; Manufacturer: Yageo; Manufacturer_Part_Number: RC0603FR-0712KL; Digi_PN: 13050531; Component_Life_Cycle_State: Reviewed; Area: 2.5; Project: LuCoV2; Power_WV_SRF: 100; Tolerance: 1
U23 = 1001907: IC REG BUCK ADJ 3A SYNC; Manufacturer: Linear Technology; Manufacturer_Part_Number: MP2316GD; Digi_PN: 17050862; Component_Life_Cycle_State: Created; Area: 6; Project: CCWMX6_SBC board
